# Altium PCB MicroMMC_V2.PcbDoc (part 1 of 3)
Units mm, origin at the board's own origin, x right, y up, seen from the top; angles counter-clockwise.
Board outline 100.01 x 100 mm, 4 copper layers (TOP01, GND02, POWER03, BOTTOM04); 302 components, 195 nets, 1017 pads, 817 vias.
Unrouted connection lines stored in the file: 7.
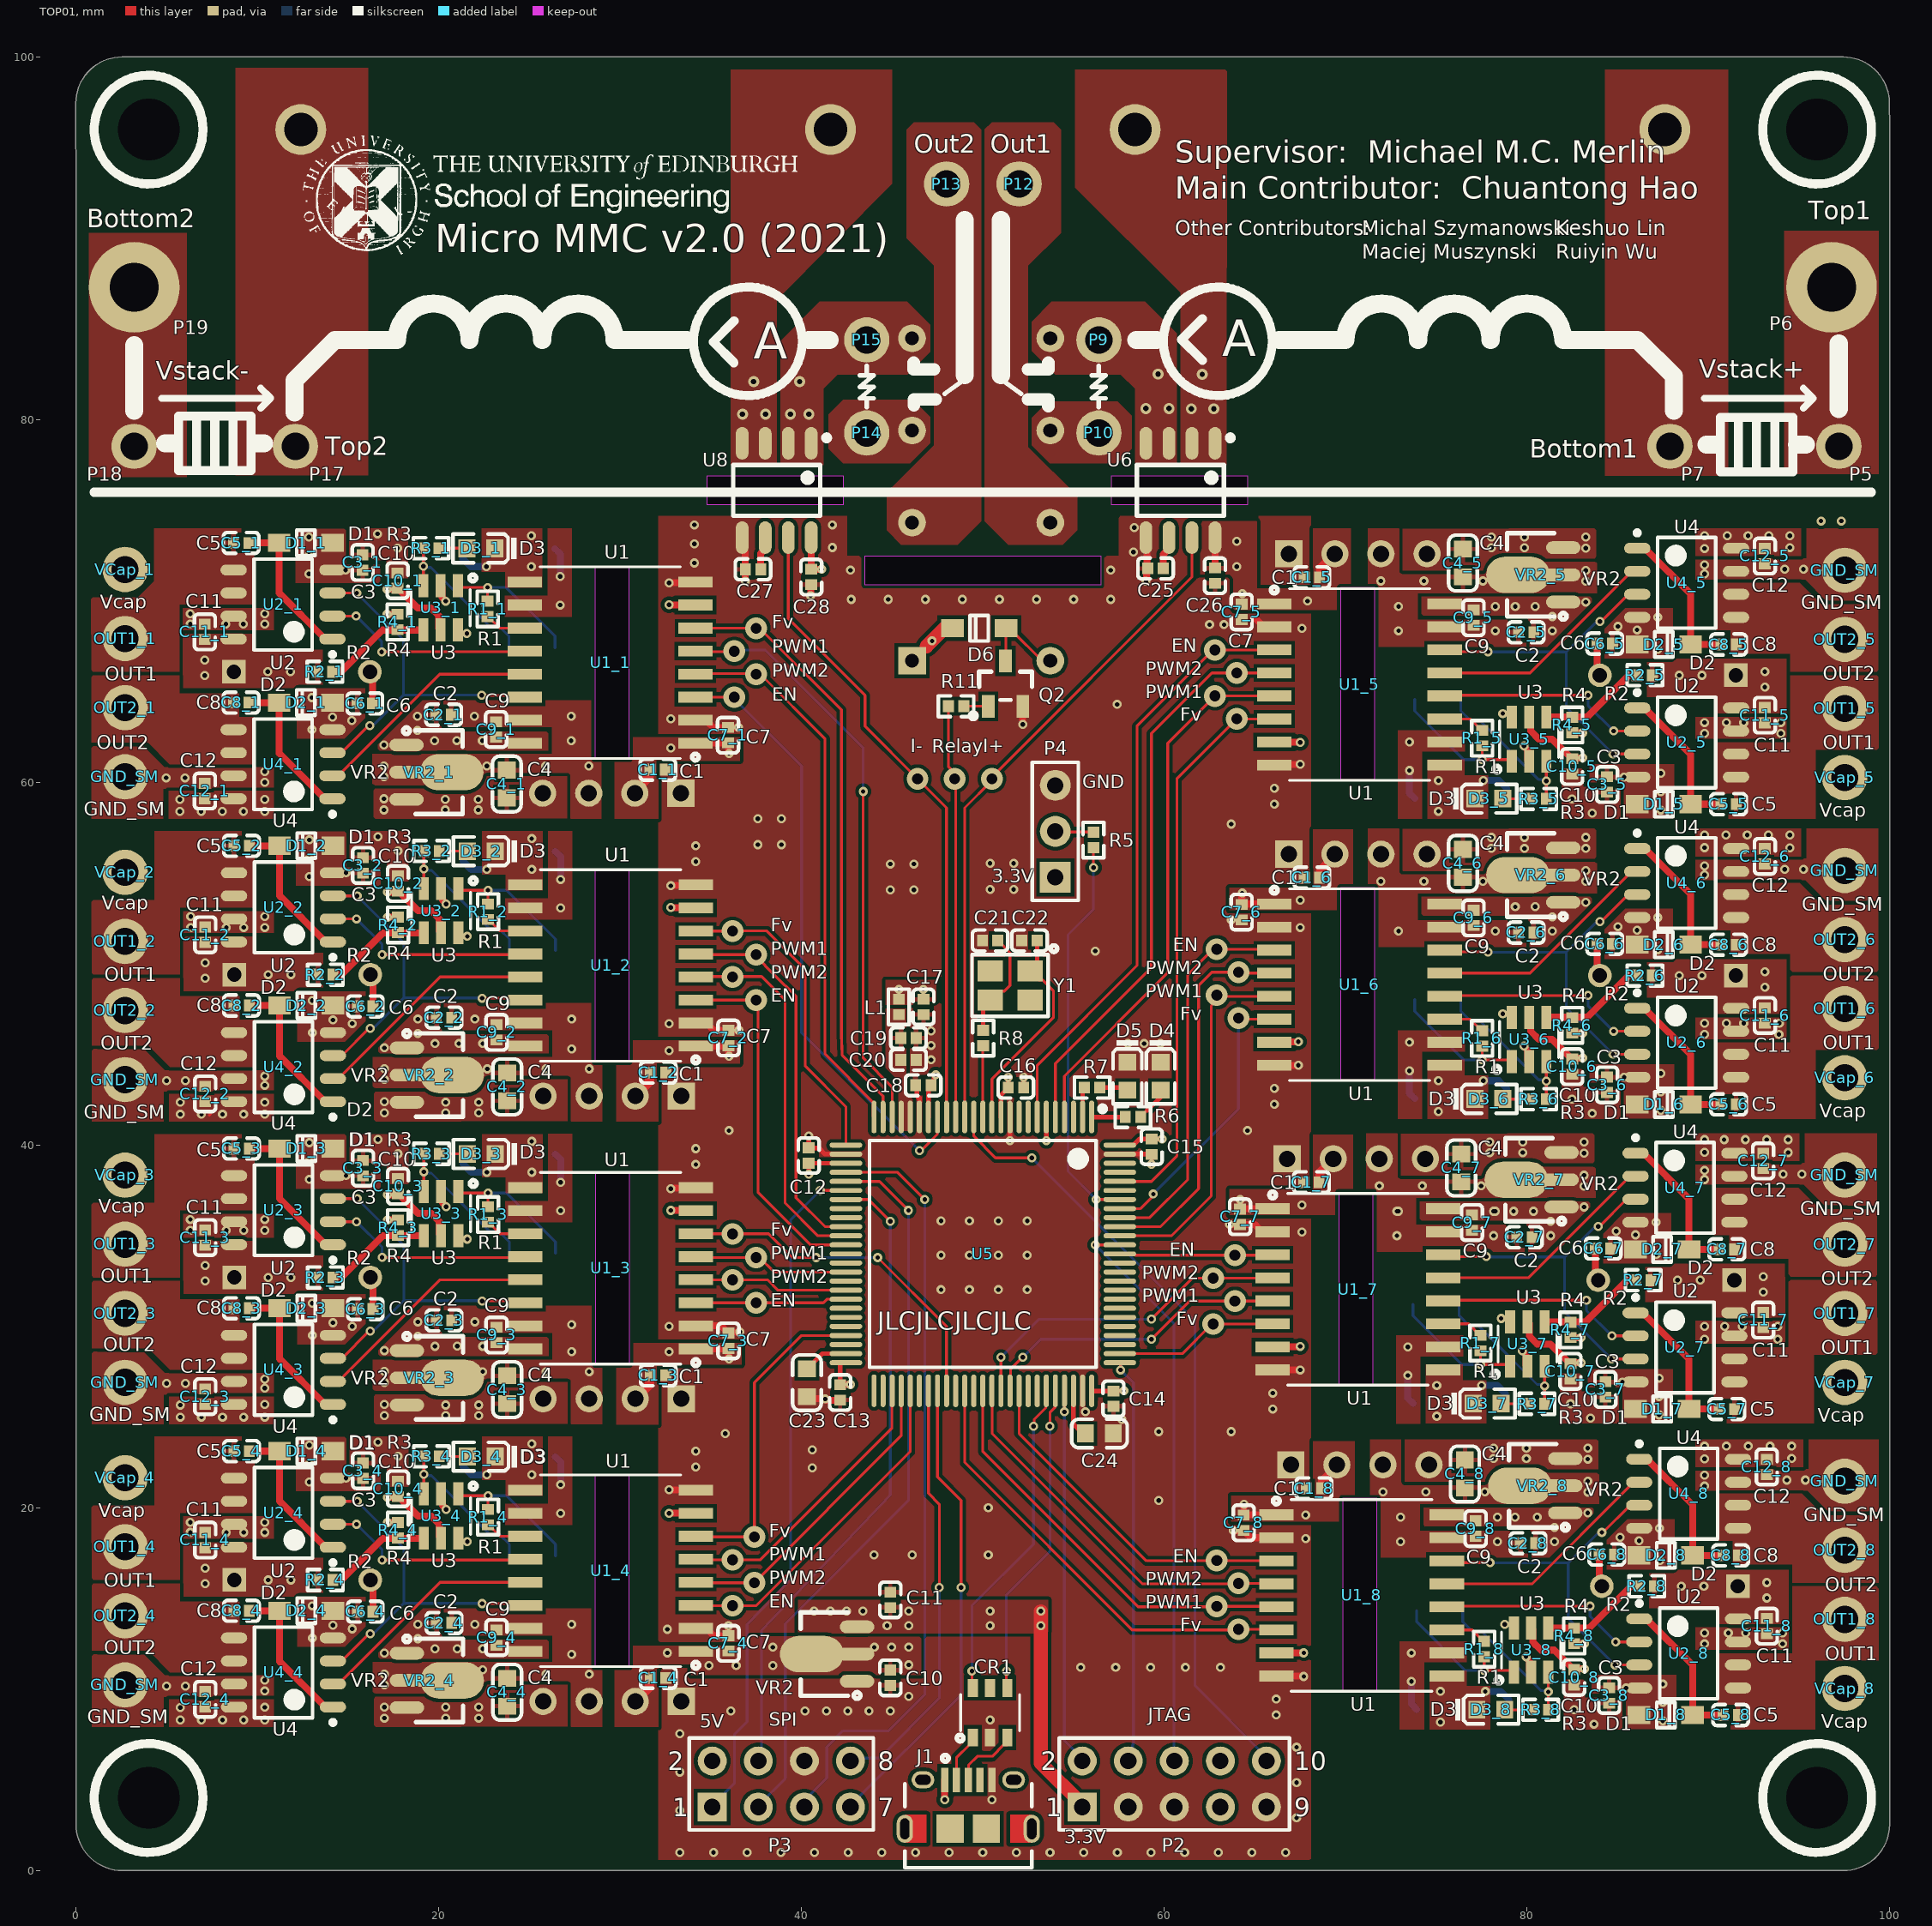
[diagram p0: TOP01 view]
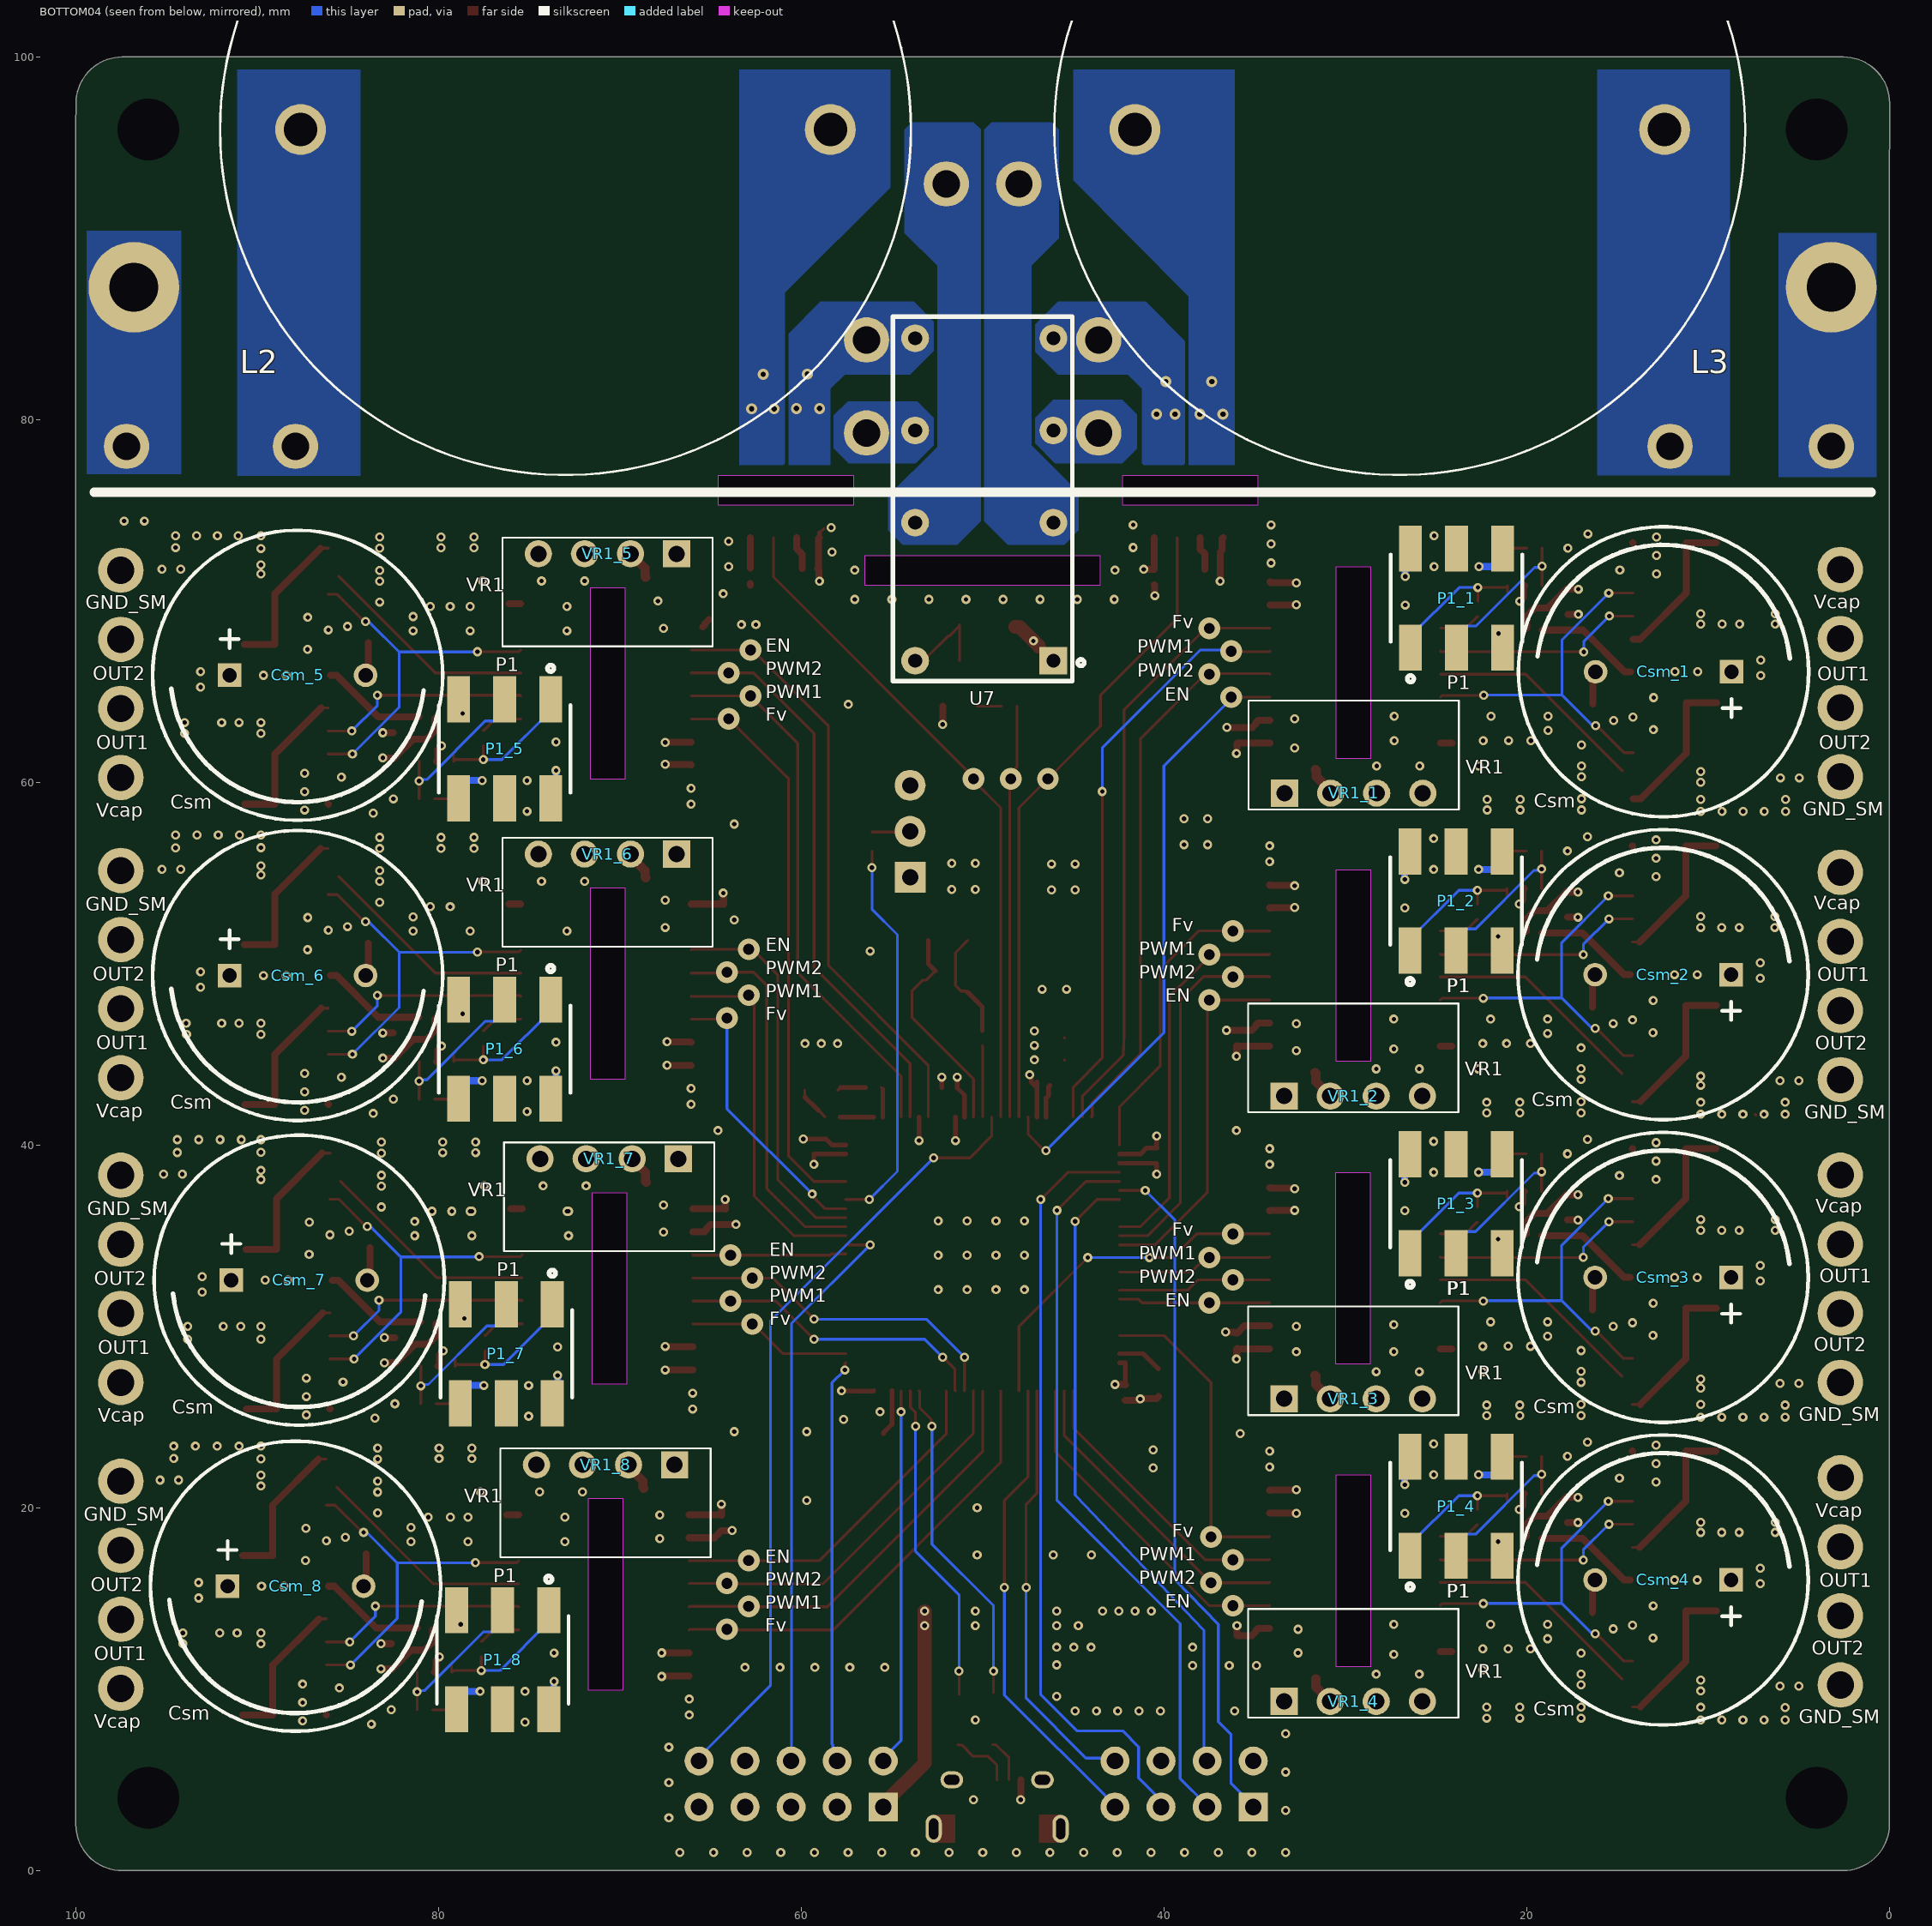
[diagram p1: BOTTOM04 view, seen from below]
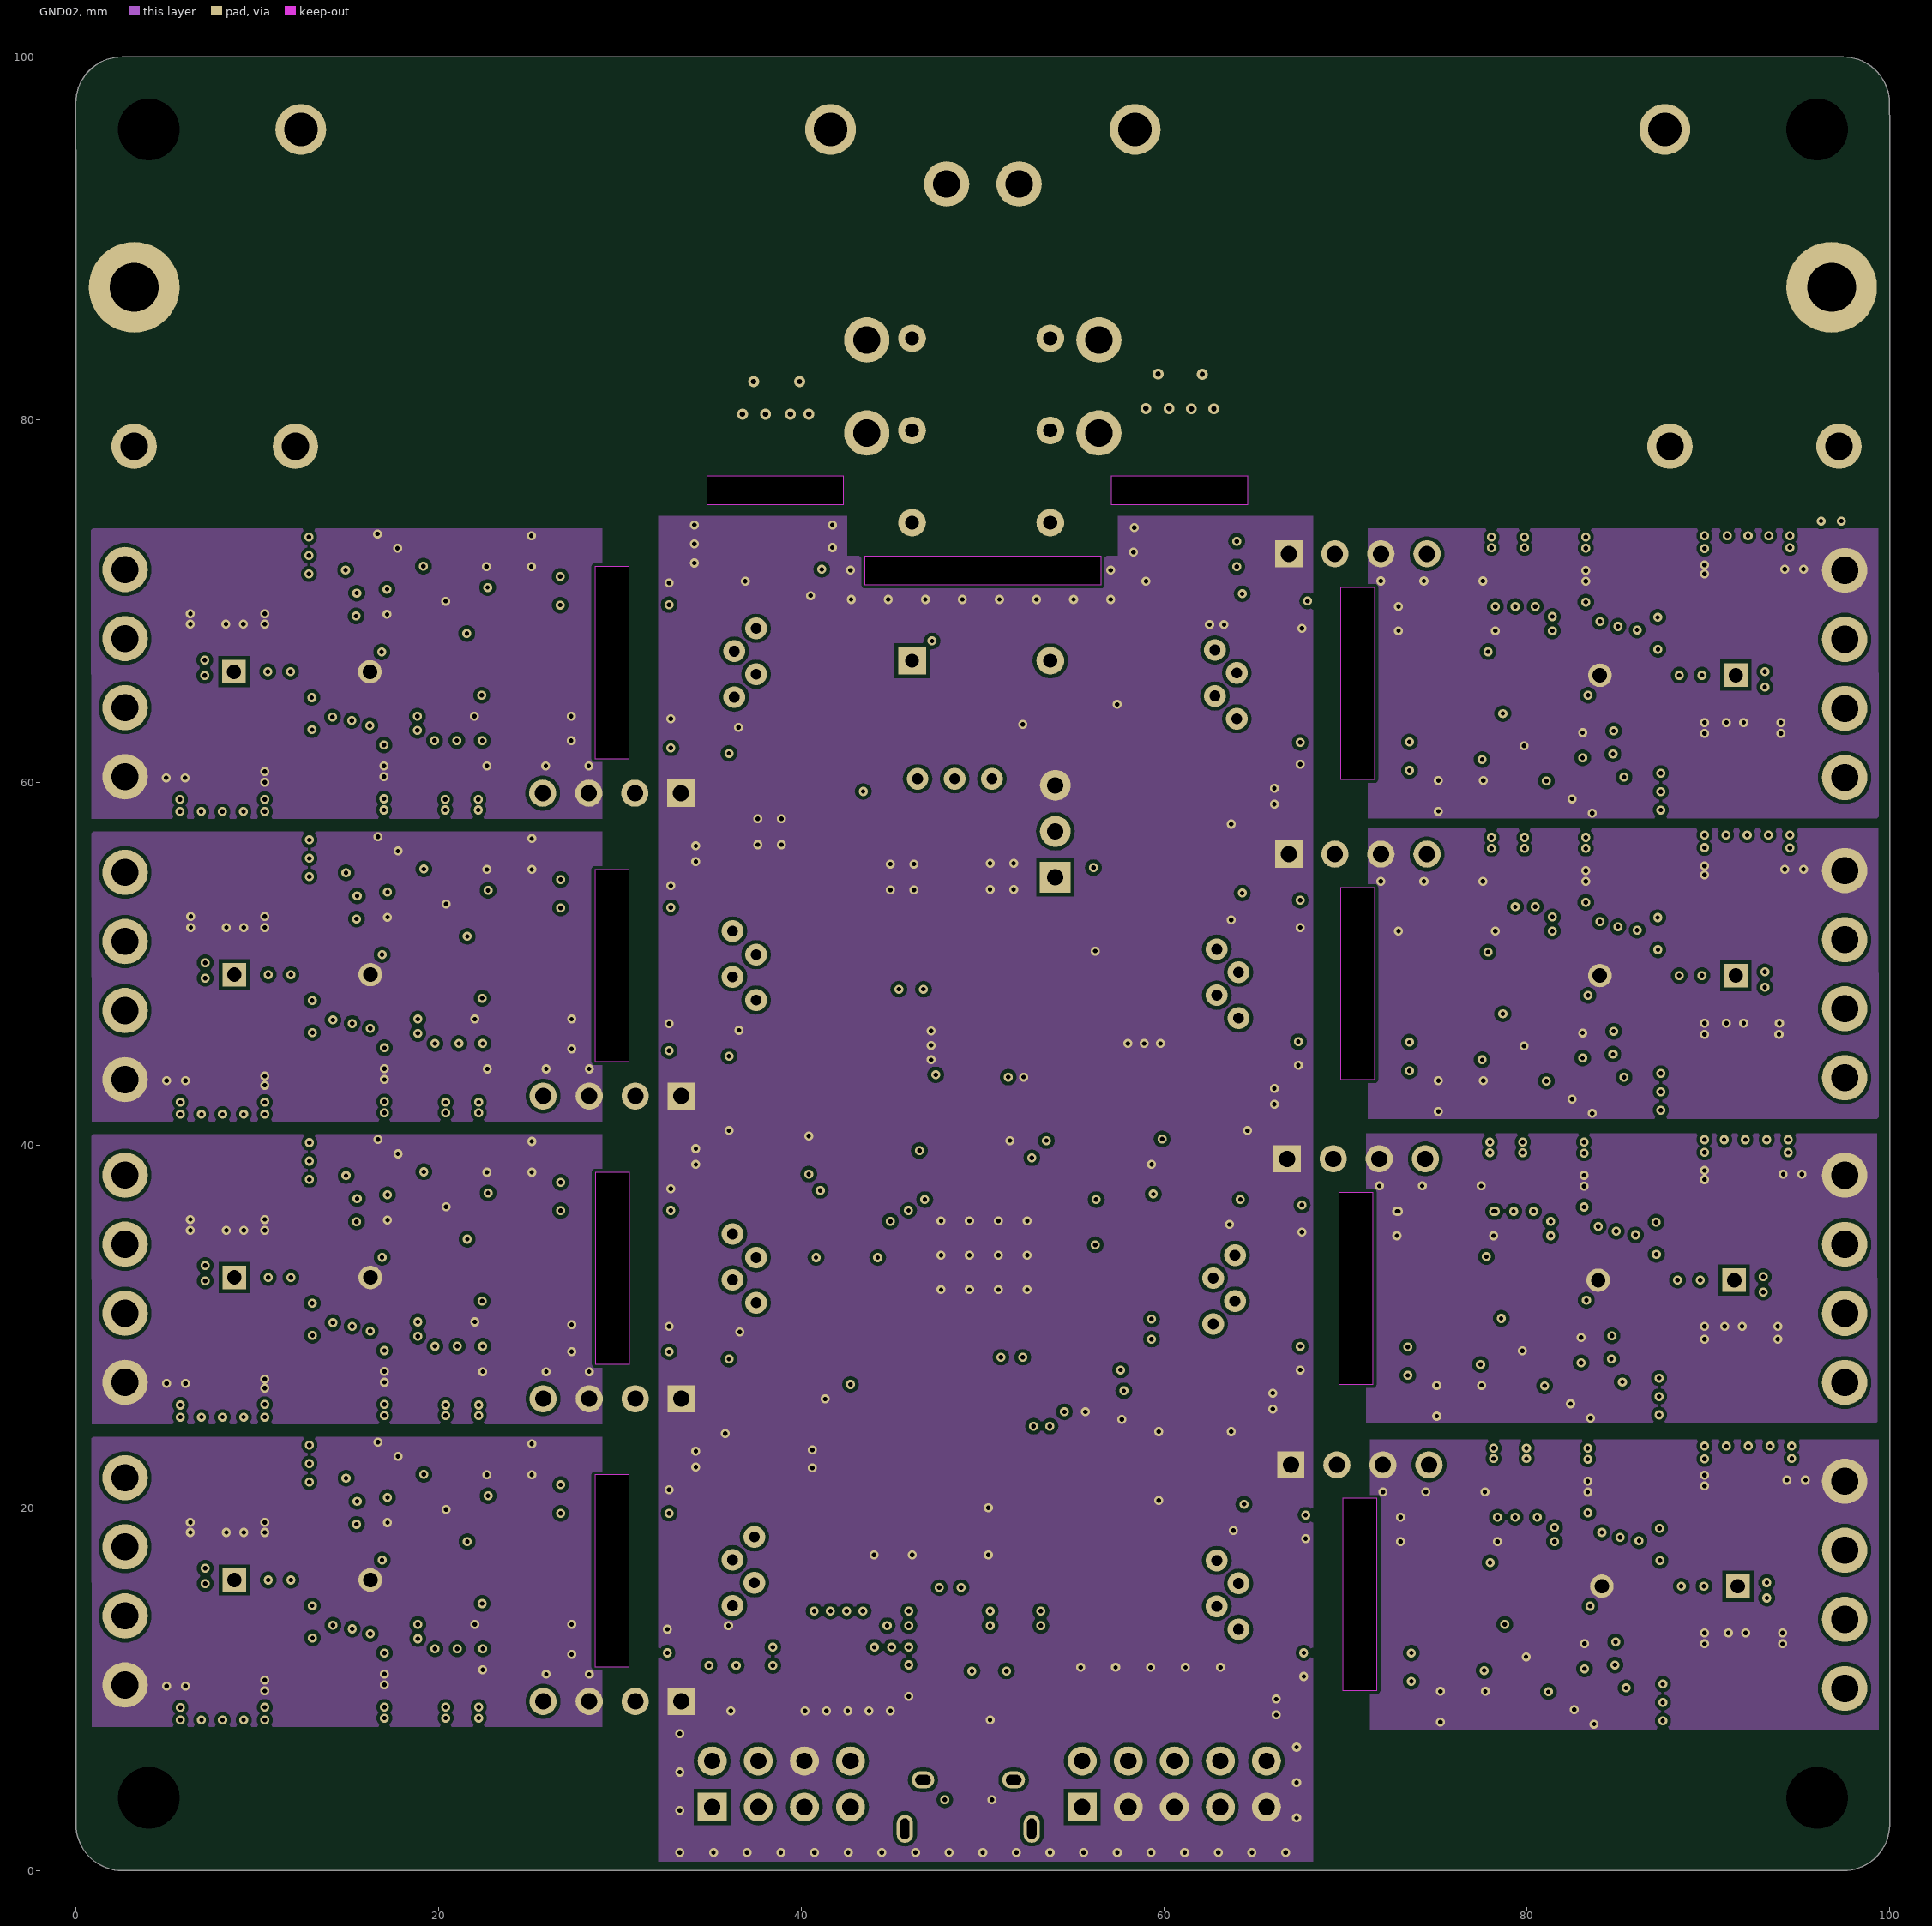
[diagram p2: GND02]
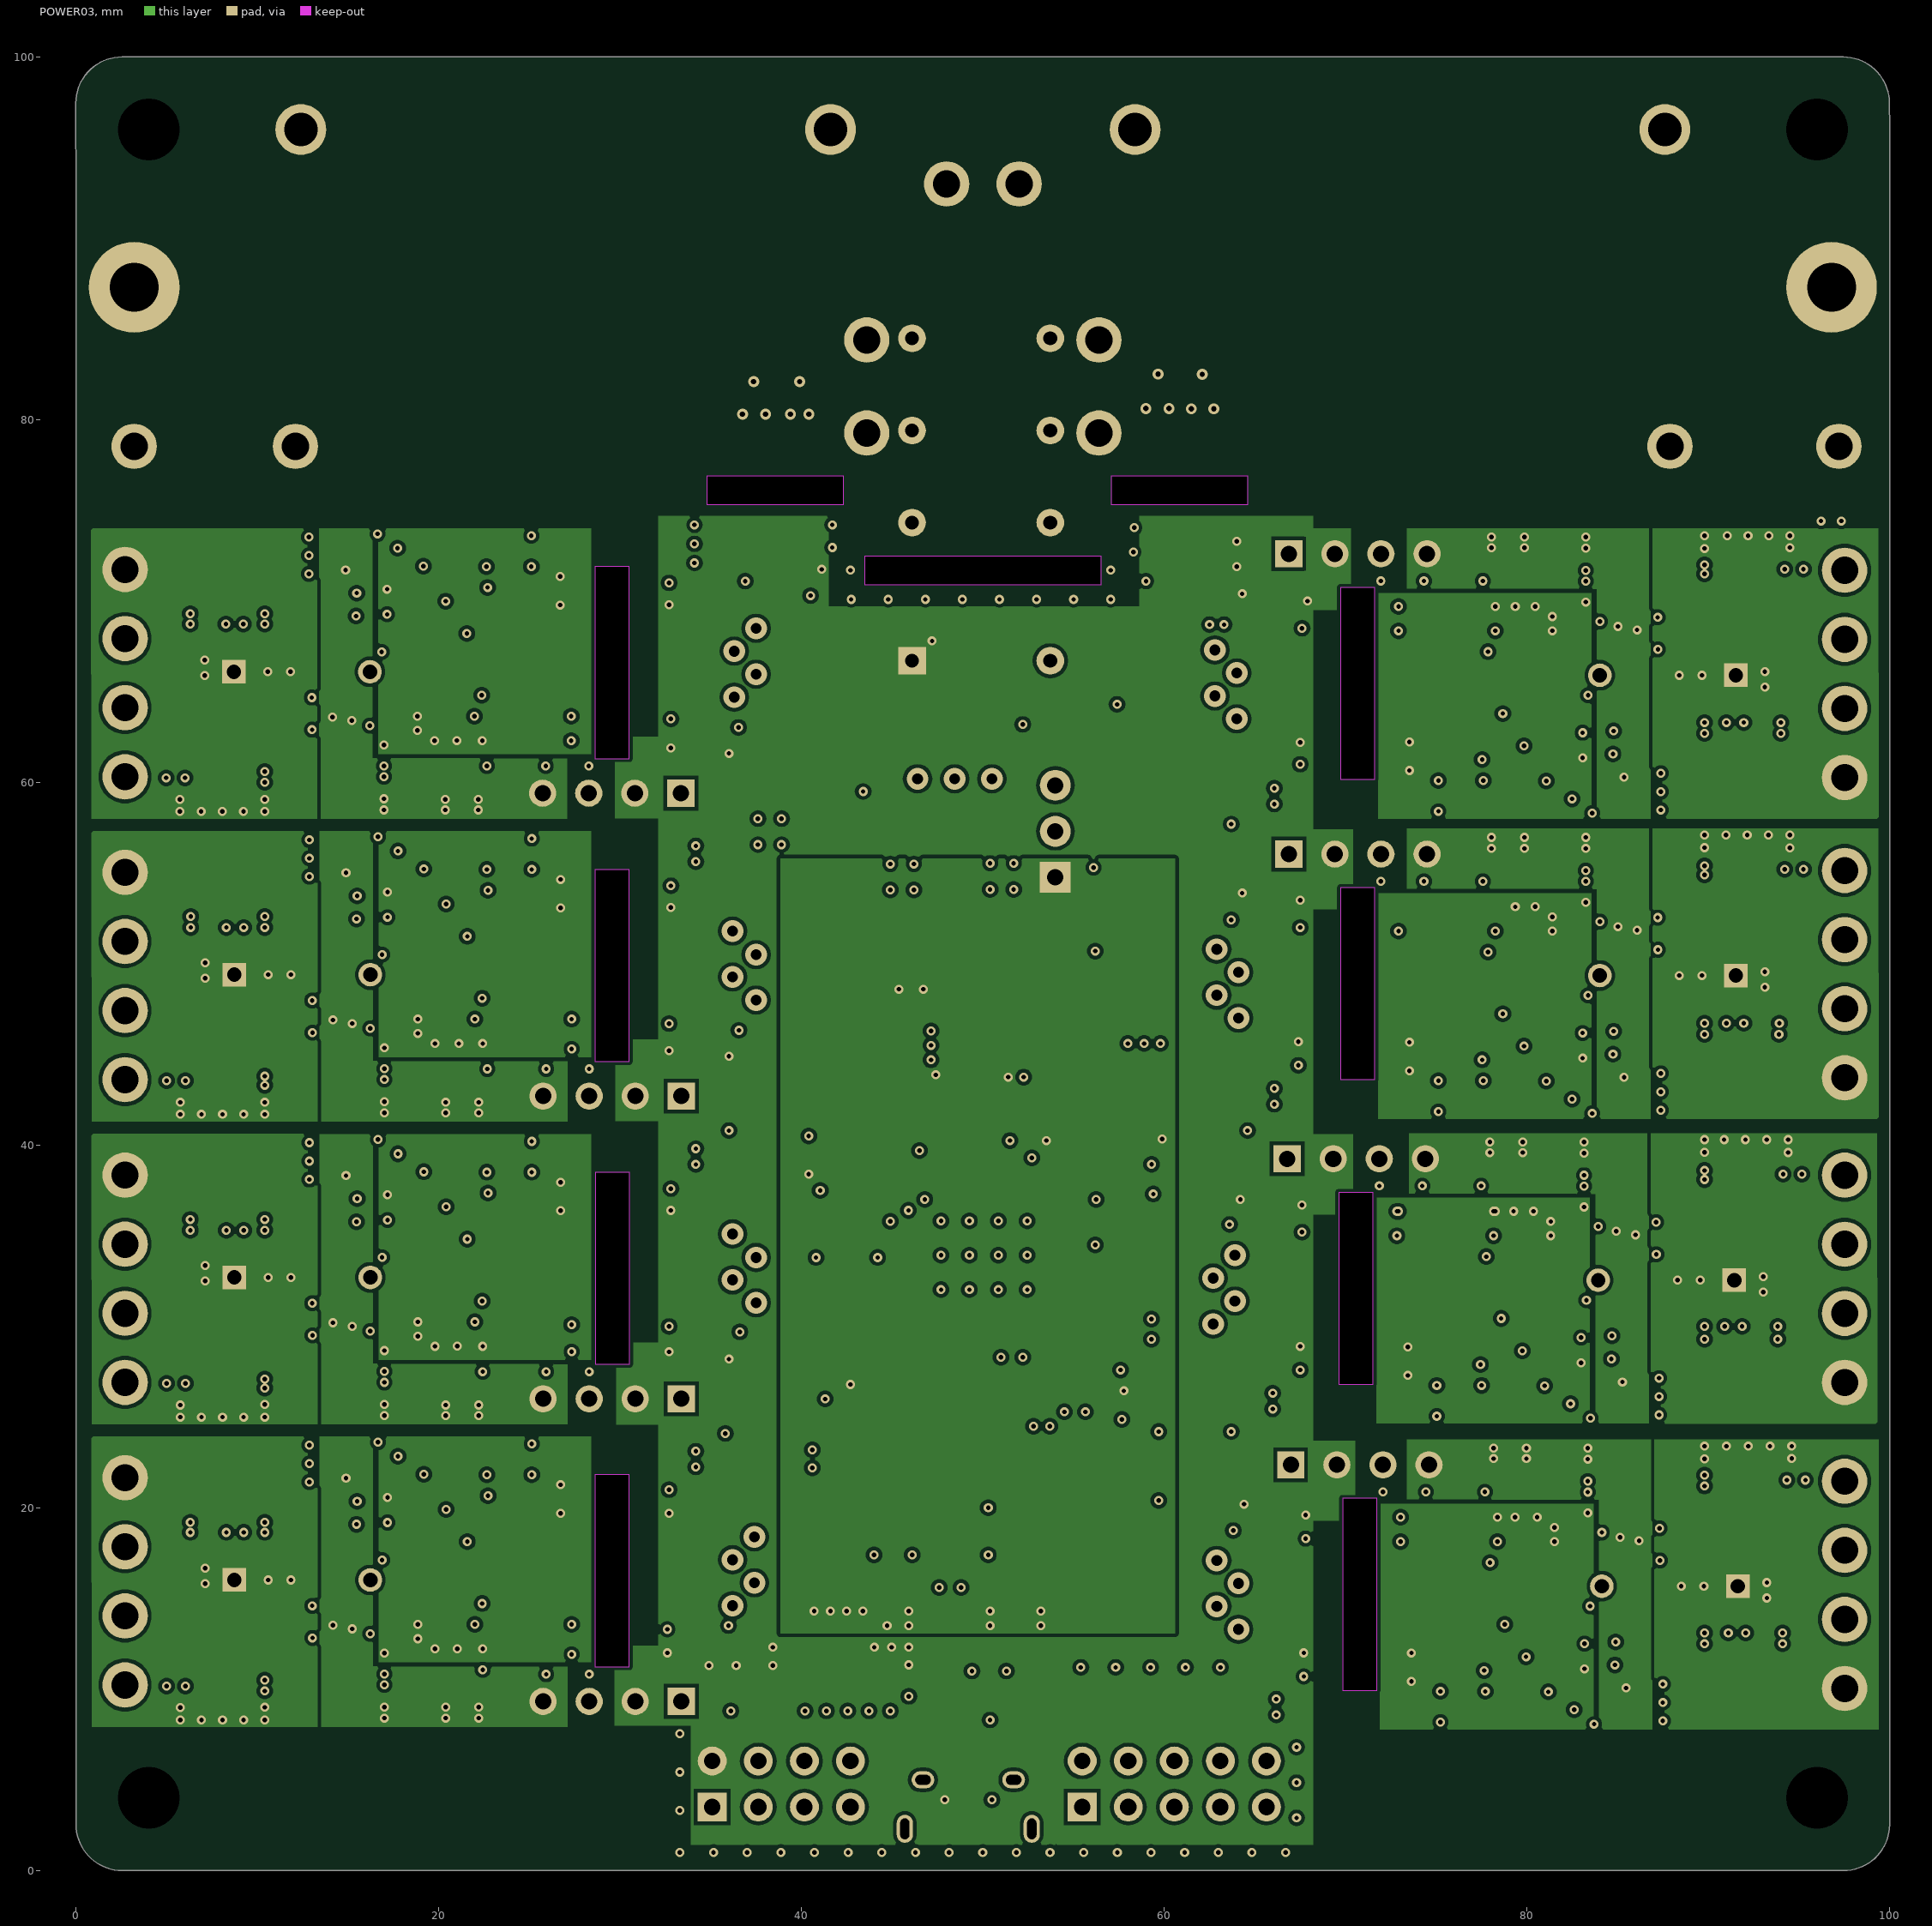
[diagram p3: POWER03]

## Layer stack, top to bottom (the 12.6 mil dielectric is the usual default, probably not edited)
Top Solder: solder mask 0.0102, Solder Resist, Dk 3.5
TOP01: signal copper 0.0356
Dielectric 1: dielectric 0.32, FR-4, Dk 4.8
GND02: signal copper 0.0356
Dielectric2: dielectric 0.32, FR-4, Dk 4.8
POWER03: signal copper 0.0356
Dielectric3: dielectric 0.32, FR-4, Dk 4.8
BOTTOM04: signal copper 0.0356
Bottom Solder: solder mask 0.0102, Solder Resist, Dk 3.5

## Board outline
2.54,0 cw(c2.54,2.54) 0,2.54 0,4.482 0,92.357 -0.012,97.46 cw(c2.528,97.46) 2.528,100 97.446,100 cw(c97.446,97.46) 99.986,97.46 100,96.167 100,2.537 cw(c97.46,2.537) 97.46,-0.003 95.335,0
cut-out: 34.8,76.9 42.3,76.9 42.3,75.3 34.8,75.3
cut-out: 71.733,9.939 71.733,20.517 69.833,20.517 69.833,9.939
cut-out: 71.532,26.813 71.532,37.391 69.632,37.391 69.632,26.813
cut-out: 71.623,43.613 71.623,54.191 69.723,54.191 69.723,43.613
cut-out: 71.623,60.169 71.623,70.747 69.723,70.747 69.723,60.169
cut-out: 28.6,21.814 28.6,11.236 30.5,11.236 30.5,21.814
cut-out: 28.624,38.499 28.624,27.921 30.524,27.921 30.524,38.499
cut-out: 28.6,71.894 28.6,61.316 30.5,61.316 30.5,71.894
cut-out: 28.6,55.189 28.6,44.611 30.5,44.611 30.5,55.189
cut-out: 43.5,72.492 56.5,72.492 56.5,70.892 43.5,70.892
cut-out: 57.1,76.9 64.6,76.9 64.6,75.3 57.1,75.3

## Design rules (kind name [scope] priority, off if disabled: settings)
Clearance [All] p1: gap=0.2 ignorepadtopadclearanceinfootprint=FALSE except(0.254: Via-Via)
Height [All] p1: minheight=0 maxheight=100 prefheight=12.7
HoleSize [All] p1: absolutevalues=TRUE maxlimit=6 minlimit=0.25 maxpercent=80.000 minpercent=20.000
HoleToHoleClearance [All] p1: gap=0.6 allowstackedmicrovias=TRUE
PlaneConnect [All] p1: planeconnectstyle=Direct reliefexpansion=0.508 reliefentries=4 reliefconductorwidth=0.254 reliefairgap=0.254
PolygonConnect [All] p1: connectstyle=Direct reliefconductorwidth=0.254 reliefentries=4 polygonreliefangle="90 Angle" airgapwidth=0.254
RoomDefinition 5 [InComponentClass('5')] p1: confinementstyle=ConfineIn formatcopy=TRUE lockcomponents=TRUE outline 63.5,74.297 99.289,74.297 99.289,57.7 63.5,57.7
RoomDefinition 8 [InComponentClass('8')] p2: confinementstyle=ConfineIn formatcopy=TRUE lockcomponents=FALSE outline 63.61,24.067 99.399,24.067 99.399,7.47 63.61,7.47
RoomDefinition 1 [InComponentClass('1')] p3: confinementstyle=ConfineIn formatcopy=TRUE lockcomponents=FALSE outline 0.611,74.297 36.4,74.297 36.4,57.7 0.611,57.7
RoomDefinition 2 [InComponentClass('2')] p4: confinementstyle=ConfineIn formatcopy=TRUE lockcomponents=FALSE outline 0.635,57.597 36.424,57.597 36.424,41 0.635,41
RoomDefinition 3 [InComponentClass('3')] p5: confinementstyle=ConfineIn formatcopy=TRUE lockcomponents=FALSE outline 0.635,40.902 36.424,40.902 36.424,24.305 0.635,24.305
RoomDefinition 4 [InComponentClass('4')] p6: confinementstyle=ConfineIn formatcopy=TRUE lockcomponents=FALSE outline 0.635,24.217 36.424,24.217 36.424,7.62 0.635,7.62
RoomDefinition 7 [InComponentClass('7')] p7: confinementstyle=ConfineIn formatcopy=TRUE lockcomponents=FALSE outline 63.409,40.941 99.198,40.941 99.198,24.344 63.409,24.344
RoomDefinition 6 [InComponentClass('6')] p8: confinementstyle=ConfineIn formatcopy=TRUE lockcomponents=FALSE outline 63.5,57.741 99.289,57.741 99.289,41.144 63.5,41.144
RoutingVias [All] p1: holewidth=1 width=2 viastyle="Through Hole" minholewidth=0.25 minwidth=0.5 maxholewidth=6 maxwidth=12
SolderMaskExpansion [All] p1: expansion=0.102 istentingtop=FALSE
UnRoutedNet [All] p1: checkbadconnections=TRUE
Width [All] p1: maxlimit=0.762 minlimit=0.152 preferedwidth=0.152
25 further rules are at their usual default settings.

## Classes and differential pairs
channel class SM_V2: 1 2 3 4 5 6 7 8
component class 2: C1_2 C2_2 C3_2 C4_2 C5_2 C6_2 C7_2 C8_2 C9_2 C10_2 C11_2 C12_2 Csm_2 D1_2 D2_2 D3_2 GND1_2 P1_2 R1_2 R2_2 R3_2 R4_2 U1_2 U2_2 U3_2 U4_2 Vcap1_2 VR1_2 VR2_2
net class TIM_Fv[8..1]: TIM_Fv1 TIM_Fv2 TIM_Fv3 TIM_Fv4 TIM_Fv5 TIM_Fv6 TIM_Fv7 TIM_Fv8
net class PWM_IN2[8..1]: PWM_IN21 PWM_IN22 PWM_IN23 PWM_IN24 PWM_IN25 PWM_IN26 PWM_IN27 PWM_IN28
net class PWM_IN1[8..1]: PWM_IN11 PWM_IN12 PWM_IN13 PWM_IN14 PWM_IN15 PWM_IN16 PWM_IN17 PWM_IN18
net class GPIO_EN[8..1]: GPIO_EN1 GPIO_EN2 GPIO_EN3 GPIO_EN4 GPIO_EN5 GPIO_EN6 GPIO_EN7 GPIO_EN8
component class Stack_V2: C25 C26 C27 C28 D6 L2 L3 P5 P6 P7 P9 P10 P12 P13 P14 P15 P17 P18 P19 Q2 R11 U6 U7 U8
component class StackController_V2: C10 C11 C12 C13 C14 C15 C16 C17 C18 C19 C20 C21 C22 C23 C24 CR1 D4 D5 J1 L1 P2 P3 P4 R5 R6 R7 R8 U5 VR2 Y1
component class 8: C1_8 C2_8 C3_8 C4_8 C5_8 C6_8 C7_8 C8_8 C9_8 C10_8 C11_8 C12_8 Csm_8 D1_8 D2_8 D3_8 GND1_8 P1_8 R1_8 R2_8 R3_8 R4_8 U1_8 U2_8 U3_8 U4_8 Vcap1_8 VR1_8 VR2_8
component class 7: C1_7 C2_7 C3_7 C4_7 C5_7 C6_7 C7_7 C8_7 C9_7 C10_7 C11_7 C12_7 Csm_7 D1_7 D2_7 D3_7 GND1_7 OUT1_7 P1_7 R1_7 R2_7 R3_7 R4_7 U1_7 U2_7 U3_7 U4_7 Vcap1_7 VR1_7 VR2_7
component class 6: C1_6 C2_6 C3_6 C4_6 C5_6 C6_6 C7_6 C8_6 C9_6 C10_6 C11_6 C12_6 Csm_6 D1_6 D2_6 D3_6 GND1_6 P1_6 R1_6 R2_6 R3_6 R4_6 U1_6 U2_6 U3_6 U4_6 Vcap1_6 VR1_6 VR2_6
component class 5: C1_5 C2_5 C3_5 C4_5 C5_5 C6_5 C7_5 C8_5 C9_5 C10_5 C11_5 C12_5 Csm_5 D1_5 D2_5 D3_5 GND1_5 OUT1_5 P1_5 R1_5 R2_5 R3_5 R4_5 U1_5 U2_5 U3_5 U4_5 Vcap1_2 Vcap1_5 VR1_5 VR2_5
component class 4: C1_4 C2_4 C3_4 C4_4 C5_4 C6_4 C7_4 C8_4 C9_4 C10_4 C11_4 C12_4 Csm_4 D1_4 D2_4 D3_4 GND1_4 P1_4 R1_4 R2_4 R3_4 R4_4 U1_4 U2_4 U3_4 U4_4 Vcap1_4 VR1_4 VR2_4
component class 3: C1_3 C2_3 C3_3 C4_3 C5_3 C6_3 C7_3 C8_3 C9_3 C10_3 C11_3 C12_3 Csm_3 D1_3 D2_3 D3_3 GND1_3 OUT1_3 P1_3 R1_3 R2_3 R3_3 R4_3 U1_3 U2_3 U3_3 U4_3 Vcap1_3 VR1_3 VR2_3
component class 1: C1_1 C2_1 C3_1 C4_1 C5_1 C6_1 C7_1 C8_1 C9_1 C10_1 C11_1 C12_1 Csm_1 D1_1 D2_1 D3_1 GND1_1 OUT1_1 P1_1 R1_1 R2_1 R3_1 R4_1 U1_1 U2_1 U3_1 U4_1 Vcap1_1 VR1_1 VR2_1

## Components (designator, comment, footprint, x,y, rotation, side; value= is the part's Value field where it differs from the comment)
C1_1 "10uF (106) ±20% 6.3V X5R" 0402_C 32.075,60.7 r180 top (schematic designator C1)
C1_2 "10uF (106) ±20% 6.3V X5R" 0402_C 32.099,44 r180 top (schematic designator C1)
C1_3 "10uF (106) ±20% 6.3V X5R" 0402_C 32.099,27.305 r180 top (schematic designator C1)
C1_4 "10uF (106) ±20% 6.3V X5R" 0402_C 32.099,10.62 r180 top (schematic designator C1)
C1_5 "10uF (106) ±20% 6.3V X5R" 0402_C 68.148,71.307 r0 top (schematic designator C1)
C1_6 "10uF (106) ±20% 6.3V X5R" 0402_C 68.148,54.751 r0 top (schematic designator C1)
C1_7 "10uF (106) ±20% 6.3V X5R" 0402_C 68.123,37.951 r0 top (schematic designator C1)
C1_8 "10uF (106) ±20% 6.3V X5R" 0402_C 68.258,21.077 r0 top (schematic designator C1)
C2_1 "10uF (106) ±20% 6.3V X5R" 0402_C 20.267,63.73 r180 top (schematic designator C2)
C2_2 "10uF (106) ±20% 6.3V X5R" 0402_C 20.291,47.03 r180 top (schematic designator C2)
C2_3 "10uF (106) ±20% 6.3V X5R" 0402_C 20.291,30.335 r180 top (schematic designator C2)
C2_4 "10uF (106) ±20% 6.3V X5R" 0402_C 20.291,13.65 r180 top (schematic designator C2)
C2_5 "10uF (106) ±20% 6.3V X5R" 0402_C 79.955,68.277 r0 top (schematic designator C2)
C2_6 "10uF (106) ±20% 6.3V X5R" 0402_C 79.955,51.721 r0 top (schematic designator C2)
C2_7 "10uF (106) ±20% 6.3V X5R" 0402_C 79.864,34.921 r0 top (schematic designator C2)
C2_8 "10uF (106) ±20% 6.3V X5R" 0402_C 80.066,18.047 r0 top (schematic designator C2)
C3_1 "1uF (105) ±10% 25V X5R" 0402_C 15.8,72.125 r270 top (schematic designator C3)
C3_2 "1uF (105) ±10% 25V X5R" 0402_C 15.824,55.425 r270 top (schematic designator C3)
C3_3 "1uF (105) ±10% 25V X5R" 0402_C 15.824,38.73 r270 top (schematic designator C3)
C3_4 "1uF (105) ±10% 25V X5R" 0402_C 15.824,22.045 r270 top (schematic designator C3)
C3_5 "1uF (105) ±10% 25V X5R" 0402_C 84.423,59.882 r90 top (schematic designator C3)
C3_6 "1uF (105) ±10% 25V X5R" 0402_C 84.423,43.326 r90 top (schematic designator C3)
C3_7 "1uF (105) ±10% 25V X5R" 0402_C 84.332,26.526 r90 top (schematic designator C3)
C3_8 "1uF (105) ±10% 25V X5R" 0402_C 84.533,9.652 r90 top (schematic designator C3)
C4_1 "10uF 16V" 0603_C 23.75,59.91 r270 top (schematic designator C4)
C4_2 "10uF 16V" 0603_C 23.773,43.21 r270 top (schematic designator C4)
C4_3 "10uF 16V" 0603_C 23.773,26.515 r270 top (schematic designator C4)
C4_4 "10uF 16V" 0603_C 23.773,9.83 r270 top (schematic designator C4)
C4_5 "10uF 16V" 0603_C 76.473,72.096 r90 top (schematic designator C4)
C4_6 "10uF 16V" 0603_C 76.473,55.54 r90 top (schematic designator C4)
C4_7 "10uF 16V" 0603_C 76.382,38.74 r90 top (schematic designator C4)
C4_8 "10uF 16V" 0603_C 76.583,21.866 r90 top (schematic designator C4)
C5_1 "1uF (105) ±10% 25V X5R" 0402_C 9.1,73.205 r180 top (schematic designator C5)
C5_2 "1uF (105) ±10% 25V X5R" 0402_C 9.124,56.505 r180 top (schematic designator C5)
C5_3 "1uF (105) ±10% 25V X5R" 0402_C 9.124,39.81 r180 top (schematic designator C5)
C5_4 "1uF (105) ±10% 25V X5R" 0402_C 9.124,23.125 r180 top (schematic designator C5)
C5_5 "1uF (105) ±10% 25V X5R" 0402_C 91.123,58.802 r0 top (schematic designator C5)
C5_6 "1uF (105) ±10% 25V X5R" 0402_C 91.123,42.246 r0 top (schematic designator C5)
C5_7 "1uF (105) ±10% 25V X5R" 0402_C 91.032,25.446 r0 top (schematic designator C5)
C5_8 "1uF (105) ±10% 25V X5R" 0402_C 91.233,8.572 r0 top (schematic designator C5)
C6_1 "1uF (105) ±10% 25V X5R" 0402_C 15.925,64.352 r180 top (schematic designator C6)
C6_2 "1uF (105) ±10% 25V X5R" 0402_C 15.949,47.652 r180 top (schematic designator C6)
C6_3 "1uF (105) ±10% 25V X5R" 0402_C 15.949,30.957 r180 top (schematic designator C6)
C6_4 "1uF (105) ±10% 25V X5R" 0402_C 15.949,14.272 r180 top (schematic designator C6)
C6_5 "1uF (105) ±10% 25V X5R" 0402_C 84.298,67.655 r0 top (schematic designator C6)
C6_6 "1uF (105) ±10% 25V X5R" 0402_C 84.298,51.099 r0 top (schematic designator C6)
C6_7 "1uF (105) ±10% 25V X5R" 0402_C 84.207,34.299 r0 top (schematic designator C6)
C6_8 "1uF (105) ±10% 25V X5R" 0402_C 84.408,17.425 r0 top (schematic designator C6)
C7_1 "100nF (104) ±10% 16V X7R" 0402_C 35.95,62.605 r270 top (schematic designator C7)
C7_2 "100nF (104) ±10% 16V X7R" 0402_C 35.973,45.905 r270 top (schematic designator C7)
C7_3 "100nF (104) ±10% 16V X7R" 0402_C 35.973,29.21 r270 top (schematic designator C7)
C7_4 "100nF (104) ±10% 16V X7R" 0402_C 35.973,12.525 r270 top (schematic designator C7)
C7_5 "100nF (104) ±10% 16V X7R" 0402_C 64.273,69.402 r90 top (schematic designator C7)
C7_6 "100nF (104) ±10% 16V X7R" 0402_C 64.273,52.846 r90 top (schematic designator C7)
C7_7 "100nF (104) ±10% 16V X7R" 0402_C 64.182,36.046 r90 top (schematic designator C7)
C7_8 "100nF (104) ±10% 16V X7R" 0402_C 64.383,19.172 r90 top (schematic designator C7)
C8_1 "1uF (105) ±10% 25V X5R" 0402_C 9.1,64.4 r180 top (schematic designator C8)
C8_2 "1uF (105) ±10% 25V X5R" 0402_C 9.124,47.7 r180 top (schematic designator C8)
C8_3 "1uF (105) ±10% 25V X5R" 0402_C 9.124,31.005 r180 top (schematic designator C8)
C8_4 "1uF (105) ±10% 25V X5R" 0402_C 9.124,14.32 r180 top (schematic designator C8)
C8_5 "1uF (105) ±10% 25V X5R" 0402_C 91.123,67.607 r0 top (schematic designator C8)
C8_6 "1uF (105) ±10% 25V X5R" 0402_C 91.123,51.051 r0 top (schematic designator C8)
C8_7 "1uF (105) ±10% 25V X5R" 0402_C 91.032,34.251 r0 top (schematic designator C8)
C8_8 "1uF (105) ±10% 25V X5R" 0402_C 91.233,17.377 r0 top (schematic designator C8)
C9_1 "100nF (104) ±10% 16V X7R" 0402_C 23.16,62.922 r270 top (schematic designator C9)
C9_2 "100nF (104) ±10% 16V X7R" 0402_C 23.184,46.222 r270 top (schematic designator C9)
C9_3 "100nF (104) ±10% 16V X7R" 0402_C 23.184,29.527 r270 top (schematic designator C9)
C9_4 "100nF (104) ±10% 16V X7R" 0402_C 23.184,12.842 r270 top (schematic designator C9)
C9_5 "100nF (104) ±10% 16V X7R" 0402_C 77.063,69.085 r90 top (schematic designator C9)
C9_6 "100nF (104) ±10% 16V X7R" 0402_C 77.063,52.529 r90 top (schematic designator C9)
C9_7 "100nF (104) ±10% 16V X7R" 0402_C 76.972,35.729 r90 top (schematic designator C9)
C9_8 "100nF (104) ±10% 16V X7R" 0402_C 77.173,18.855 r90 top (schematic designator C9)
C10 "10uF (106) ±20% 6.3V X5R" 0402_C 44.9,10.625 r90 top
C10_1 "100nF (104) ±10% 16V X7R" 0402_C 17.725,71.127 r270 top (schematic designator C10)
C10_2 "100nF (104) ±10% 16V X7R" 0402_C 17.749,54.427 r270 top (schematic designator C10)
C10_3 "100nF (104) ±10% 16V X7R" 0402_C 17.749,37.731 r270 top (schematic designator C10)
C10_4 "100nF (104) ±10% 16V X7R" 0402_C 17.749,21.047 r270 top (schematic designator C10)
C10_5 "100nF (104) ±10% 16V X7R" 0402_C 82.498,60.88 r90 top (schematic designator C10)
C10_6 "100nF (104) ±10% 16V X7R" 0402_C 82.498,44.324 r90 top (schematic designator C10)
C10_7 "100nF (104) ±10% 16V X7R" 0402_C 82.407,27.524 r90 top (schematic designator C10)
C10_8 "100nF (104) ±10% 16V X7R" 0402_C 82.608,10.65 r90 top (schematic designator C10)
C11 "10uF (106) ±20% 6.3V X5R" 0402_C 44.9,14.925 r270 top
C11_1 "1uF (105) ±10% 25V X5R" 0402_C 7.1,68.3 r270 top (schematic designator C11)
C11_2 "1uF (105) ±10% 25V X5R" 0402_C 7.124,51.6 r270 top (schematic designator C11)
C11_3 "1uF (105) ±10% 25V X5R" 0402_C 7.124,34.905 r270 top (schematic designator C11)
C11_4 "1uF (105) ±10% 25V X5R" 0402_C 7.124,18.22 r270 top (schematic designator C11)
C11_5 "1uF (105) ±10% 25V X5R" 0402_C 93.123,63.707 r90 top (schematic designator C11)
C11_6 "1uF (105) ±10% 25V X5R" 0402_C 93.123,47.151 r90 top (schematic designator C11)
C11_7 "1uF (105) ±10% 25V X5R" 0402_C 93.032,30.351 r90 top (schematic designator C11)
C11_8 "1uF (105) ±10% 25V X5R" 0402_C 93.233,13.477 r90 top (schematic designator C11)
C12 "4.7uF (475) ±20% 10V X5R" 0402_C 40.4,39.425 r270 top
C12_1 "1uF (105) ±10% 25V X5R" 0402_C 7.1,59.525 r270 top (schematic designator C12)
C12_2 "1uF (105) ±10% 25V X5R" 0402_C 7.124,42.825 r270 top (schematic designator C12)
C12_3 "1uF (105) ±10% 25V X5R" 0402_C 7.124,26.13 r270 top (schematic designator C12)
C12_4 "1uF (105) ±10% 25V X5R" 0402_C 7.124,9.445 r270 top (schematic designator C12)
C12_5 "1uF (105) ±10% 25V X5R" 0402_C 93.123,72.482 r90 top (schematic designator C12)
C12_6 "1uF (105) ±10% 25V X5R" 0402_C 93.123,55.926 r90 top (schematic designator C12)
C12_7 "1uF (105) ±10% 25V X5R" 0402_C 93.032,39.126 r90 top (schematic designator C12)
C12_8 "1uF (105) ±10% 25V X5R" 0402_C 93.233,22.252 r90 top (schematic designator C12)
C13 "100nF (104) ±10% 16V X7R" 0402_C 42.134,26.361 r90 top
C14 "100nF (104) ±10% 16V X7R" 0402_C 57.2,26.016 r90 top
C15 "100nF (104) ±10% 16V X7R" 0402_C 59.311,39.914 r90 top
C16 "100nF (104) ±10% 16V X7R" 0402_C 51.826,43.175 r180 top
C17 "100nF (104) ±10% 16V X7R" 0402_C 46.726,47.619 r90 top
C18 "100nF (104) ±10% 16V X7R" 0402_C 46.715,43.3 r0 top
C19 "1uF (105) ±10% 25V X5R" 0402_C 45.9,45.9 r0 top
C20 "100nF (104) ±10% 16V X7R" 0402_C 45.9,44.7 r180 top
C21 "12pF (120) ±5% 50V C0G" 0402_C 50.4,51.283 r0 top
C22 "12pF (120) ±5% 50V C0G" 0402_C 52.574,51.283 r0 top
C23 "2.2uF (225) ±10% 16V X5R" 0603_C 40.3,26.9 r90 top
C24 "2.2uF (225) ±10% 16V X5R" 0603_C 56.43,24.1 r180 top
C25 "1nF (102) ±10% 50V X7R" 0402_C 59.525,71.8 r0 top
C26 "100nF (104) ±10% 16V X7R" 0402_C 62.803,71.4 r90 top
C27 "1nF (102) ±10% 50V X7R" 0402_C 37.328,71.75 r0 top
C28 "100nF (104) ±10% 16V X7R" 0402_C 40.54,71.325 r90 top
CR1 "USBLC6-2SC6" SOT23-6L_STM 50.4,8.7 r0 top
Csm_1 "6800uF 16V" "6800UF 16V 16*25" 8.7,66.1 r0 bottom (schematic designator Csm)
Csm_2 "6800uF 16V" "6800UF 16V 16*25" 8.724,49.4 r0 bottom (schematic designator Csm)
Csm_3 "6800uF 16V" "6800UF 16V 16*25" 8.724,32.705 r0 bottom (schematic designator Csm)
Csm_4 "6800uF 16V" "6800UF 16V 16*25" 8.724,16.02 r0 bottom (schematic designator Csm)
Csm_5 "6800uF 16V" "6800UF 16V 16*25" 91.523,65.907 r180 bottom (schematic designator Csm)
Csm_6 "6800uF 16V" "6800UF 16V 16*25" 91.523,49.351 r180 bottom (schematic designator Csm)
Csm_7 "6800uF 16V" "6800UF 16V 16*25" 91.432,32.551 r180 bottom (schematic designator Csm)
Csm_8 "6800uF 16V" "6800uF 16V 16*25" 87.883,15.677 r180 bottom (schematic designator Csm)
D1_1 "B5819W" SOD-123 12.67,73.205 r0 top (schematic designator D1)
D1_2 "B5819W" SOD-123 12.694,56.505 r0 top (schematic designator D1)
D1_3 "B5819W" SOD-123 12.694,39.81 r0 top (schematic designator D1)
D1_4 "B5819W" SOD-123 12.694,23.125 r0 top (schematic designator D1)
D1_5 "B5819W" SOD-123 87.552,58.802 r180 top (schematic designator D1)
D1_6 "B5819W" SOD-123 87.552,42.246 r180 top (schematic designator D1)
D1_7 "B5819W" SOD-123 87.461,25.446 r180 top (schematic designator D1)
D1_8 "B5819W" SOD-123 87.663,8.572 r180 top (schematic designator D1)
D2_1 "B5819W" SOD-123 12.67,64.4 r0 top (schematic designator D2)
D2_2 "B5819W" SOD-123 12.694,47.7 r0 top (schematic designator D2)
D2_3 "B5819W" SOD-123 12.694,31.005 r0 top (schematic designator D2)
D2_4 "B5819W" SOD-123 12.694,14.32 r0 top (schematic designator D2)
D2_5 "B5819W" SOD-123 87.552,67.607 r180 top (schematic designator D2)
D2_6 "B5819W" SOD-123 87.552,51.051 r180 top (schematic designator D2)
D2_7 "B5819W" SOD-123 87.461,34.251 r180 top (schematic designator D2)
D2_8 "B5819W" SOD-123 87.663,17.377 r180 top (schematic designator D2)
D3_1 "LED_灯_红_Iv=100-120_λd=615-630" 0603_LED_S1 22.32,72.905 r180 top (schematic designator D3)
D3_2 "LED_灯_红_Iv=100-120_λd=615-630" 0603_LED_S1 22.343,56.205 r180 top (schematic designator D3)
D3_3 "LED_灯_红_Iv=100-120_λd=615-630" 0603_LED_S1 22.343,39.51 r180 top (schematic designator D3)
D3_4 "LED_灯_红_Iv=100-120_λd=615-630" 0603_LED_S1 22.343,22.825 r180 top (schematic designator D3)
D3_5 "LED_灯_红_Iv=100-120_λd=615-630" 0603_LED_S1 77.903,59.102 r0 top (schematic designator D3)
D3_6 "LED_灯_红_Iv=100-120_λd=615-630" 0603_LED_S1 77.903,42.546 r0 top (schematic designator D3)
D3_7 "LED_灯_红_Iv=100-120_λd=615-630" 0603_LED_S1 77.812,25.746 r0 top (schematic designator D3)
D3_8 "LED_灯_红_Iv=100-120_λd=615-630" 0603_LED_S1 78.013,8.872 r0 top (schematic designator D3)
D4 "LED_灯_红_Iv=100-120_λd=615-630" 0603_LED_S1 59.801,43.805 r270 top
D5 "LED_灯_绿_Iv=112-285_λd=520-535" 0603_LED_S1 57.975,43.805 r270 top
D6 "B5819W" SOD-123 49.8,68.5 r0 top
GND_SM "4MMx1MM5" "PAD WITH HOLE"#1 97.523,21.467 r270 top (schematic designator OUT2)
GND_SM "4MMx1MM5" "PAD WITH HOLE"#2 2.458,60.54 r90 top (schematic designator OUT2)
GND_SM "4MMx1MM5" "PAD WITH HOLE"#1 2.7,43.61 r90 top (schematic designator OUT2)
GND_SM "4MMx1MM5" "PAD WITH HOLE"#1 2.7,26.915 r90 top (schematic designator OUT2)
GND_SM "4MMx1MM5" "PAD WITH HOLE"#1 2.7,10.23 r90 top (schematic designator OUT2)
GND_SM "4MMx1MM5" "PAD WITH HOLE"#3 97.523,71.824 r270 top (schematic designator OUT2)
GND_SM "4MMx1MM5" "PAD WITH HOLE"#1 97.523,55.141 r270 top (schematic designator OUT2)
GND_SM "4MMx1MM5" "PAD WITH HOLE"#1 97.523,38.341 r270 top (schematic designator OUT2)
J1 "10118194-0001LF" FCI-10118194-0001LF-5_V 49.2,3.65 r0 top
L1 "39nH" 0402_L 45.366,47.619 r270 top
L2 "1140-122K-RC" INDRD2921W163D3810H2616P 73,96 r180 bottom
L3 "1140-122K-RC" INDRD2921W163D3810H2616P 27,96 r180 bottom
OUT1_1 "4MMx1MM5" "PAD WITH HOLE"#4 2.528,67.129 r90 top (schematic designator GND1)
OUT1_2 "4MMx1MM5" "PAD WITH HOLE"#1 2.7,51.23 r90 top (schematic designator GND1)
OUT1_3 "4MMx1MM5" "PAD WITH HOLE"#1 2.7,34.535 r90 top (schematic designator GND1)
OUT1_4 "4MMx1MM5" "PAD WITH HOLE"#1 2.7,17.85 r90 top (schematic designator GND1)
OUT1_5 "4MMx1MM5" "PAD WITH HOLE"#5 97.523,64.262 r270 top (schematic designator GND1)
OUT1_6 "4MMx1MM5" "PAD WITH HOLE"#1 97.523,47.521 r270 top (schematic designator GND1)
OUT1_7 "4MMx1MM5" "PAD WITH HOLE"#1 97.523,30.721 r270 top (schematic designator GND1)
OUT1_8 "4MMx1MM5" "PAD WITH HOLE"#1 97.523,13.847 r270 top (schematic designator GND1)
OUT2_1 "4MMx1MM5" "PAD WITH HOLE"#6 1.871,64.781 r90 top (schematic designator Vcap1)
OUT2_2 "4MMx1MM5" "PAD WITH HOLE"#1 2.7,47.42 r90 top (schematic designator Vcap1)
OUT2_3 "4MMx1MM5" "PAD WITH HOLE"#1 2.7,30.725 r90 top (schematic designator Vcap1)
OUT2_4 "4MMx1MM5" "PAD WITH HOLE"#1 2.7,14.04 r90 top (schematic designator Vcap1)
OUT2_5 "4MMx1MM5" "PAD WITH HOLE"#7 97.523,67.503 r270 top (schematic designator Vcap1)
OUT2_6 "4MMx1MM5" "PAD WITH HOLE"#1 97.523,51.331 r270 top (schematic designator Vcap1)
OUT2_7 "4MMx1MM5" "PAD WITH HOLE"#1 97.523,34.531 r270 top (schematic designator Vcap1)
OUT2_8 "4MMx1MM5" "PAD WITH HOLE"#1 97.523,17.657 r270 top (schematic designator Vcap1)
P1_1 "95278-101A06LF" AMPM-95278-101A06LF_V 23.867,70.16 r180 bottom (schematic designator P1)
P1_2 "95278-101A06LF" AMPM-95278-101A06LF_V 23.891,53.46 r180 bottom (schematic designator P1)
P1_3 "95278-101A06LF" AMPM-95278-101A06LF_V 23.891,36.765 r180 bottom (schematic designator P1)
P1_4 "95278-101A06LF" AMPM-95278-101A06LF_V 23.891,20.08 r180 bottom (schematic designator P1)
P1_5 "95278-101A06LF" AMPM-95278-101A06LF_V 76.355,61.847 r0 bottom (schematic designator P1)
P1_6 "95278-101A06LF" AMPM-95278-101A06LF_V 76.355,45.291 r0 bottom (schematic designator P1)
P1_7 "95278-101A06LF" AMPM-95278-101A06LF_V 76.264,28.491 r0 bottom (schematic designator P1)
P1_8 "95278-101A06LF" AMPM-95278-101A06LF_V 76.466,11.617 r0 bottom (schematic designator P1)
P2 "Header 5X2" HDR2.54-LI-2x5P 60.56,4.77 r0 top
P3 "Header 4X2" HDR2.54-LI-2x4P 38.89,4.77 r0 top
P4 "Header 3" HDR2.54-LI-3P 54,57.3 r90 top
P5 "4MMx1MM5" "PAD WITH HOLE"#8 99.645,79.209 r0 top
P6 "4MMx1MM5" "PAD WITH HOLE"#9 97.695,100.432 r0 top
P7 "4MMx1MM5" "PAD WITH HOLE"#10 89.951,78.447 r0 top
P9 "4MMx1MM5" "PAD WITH HOLE"#11 56.572,84.397 r0 top
P10 "4MMx1MM5" "PAD WITH HOLE"#11 56.572,79.266 r0 top
P12 "4MMx1MM5" "PAD WITH HOLE"#12 56.572,74.249 r0 top
P13 "4MMx1MM5" "PAD WITH HOLE"#13 43.4,74.249 r0 top
P14 "4MMx1MM5" "PAD WITH HOLE"#14 43.4,79.266 r0 top
P15 "4MMx1MM5" "PAD WITH HOLE"#15 43.283,84.397 r0 top
P17 "4MMx1MM5" "PAD WITH HOLE"#16 9.795,78.574 r0 top
P18 "4MMx1MM5" "PAD WITH HOLE"#17 1.345,78.574 r0 top
P19 "4MMx1MM5" "PAD WITH HOLE"#18 2.495,100.559 r0 top
Q2 "2N7002" SOT-23(SOT-23-3) 51.25,65.45 r270 top
R1_1 "1KΩ (1001) ±1%" 0402_R 22.69,69.568 r90 top (schematic designator R1)
R1_2 "1KΩ (1001) ±1%" 0402_R 22.713,52.868 r90 top (schematic designator R1)
R1_3 "1KΩ (1001) ±1%" 0402_R 22.713,36.173 r90 top (schematic designator R1)
R1_4 "1KΩ (1001) ±1%" 0402_R 22.713,19.488 r90 top (schematic designator R1)
R1_5 "1KΩ (1001) ±1%" 0402_R 77.533,62.439 r270 top (schematic designator R1)
R1_6 "1KΩ (1001) ±1%" 0402_R 77.533,45.883 r270 top (schematic designator R1)
R1_7 "1KΩ (1001) ±1%" 0402_R 77.442,29.083 r270 top (schematic designator R1)
R1_8 "1KΩ (1001) ±1%" 0402_R 77.643,12.209 r270 top (schematic designator R1)
R2_1 "100KΩ (1003) ±1%" 0402_R 13.72,66.1 r180 top (schematic designator R2)
R2_2 "100KΩ (1003) ±1%" 0402_R 13.744,49.4 r180 top (schematic designator R2)
R2_3 "100KΩ (1003) ±1%" 0402_R 13.744,32.705 r180 top (schematic designator R2)
R2_4 "100KΩ (1003) ±1%" 0402_R 13.744,16.02 r180 top (schematic designator R2)
R2_5 "100KΩ (1003) ±1%" 0402_R 86.502,65.907 r0 top (schematic designator R2)
R2_6 "100KΩ (1003) ±1%" 0402_R 86.502,49.351 r0 top (schematic designator R2)
R2_7 "100KΩ (1003) ±1%" 0402_R 86.411,32.551 r0 top (schematic designator R2)
R2_8 "100KΩ (1003) ±1%" 0402_R 86.613,15.677 r0 top (schematic designator R2)
R3_1 "2.4KΩ (2401) ±1%" 0402_R 19.575,72.915 r180 top (schematic designator R3)
R3_2 "2.4KΩ (2401) ±1%" 0402_R 19.598,56.215 r180 top (schematic designator R3)
R3_3 "2.4KΩ (2401) ±1%" 0402_R 19.598,39.52 r180 top (schematic designator R3)
R3_4 "2.4KΩ (2401) ±1%" 0402_R 19.598,22.835 r180 top (schematic designator R3)
R3_5 "2.4KΩ (2401) ±1%" 0402_R 80.648,59.092 r0 top (schematic designator R3)
R3_6 "2.4KΩ (2401) ±1%" 0402_R 80.648,42.536 r0 top (schematic designator R3)
R3_7 "2.4KΩ (2401) ±1%" 0402_R 80.557,25.736 r0 top (schematic designator R3)
R3_8 "2.4KΩ (2401) ±1%" 0402_R 80.758,8.862 r0 top (schematic designator R3)
R4_1 "47KΩ (4702) ±1%" 0402_R 17.725,68.843 r270 top (schematic designator R4)
R4_2 "47KΩ (4702) ±1%" 0402_R 17.749,52.143 r270 top (schematic designator R4)
R4_3 "47KΩ (4702) ±1%" 0402_R 17.749,35.448 r270 top (schematic designator R4)
R4_4 "47KΩ (4702) ±1%" 0402_R 17.749,18.763 r270 top (schematic designator R4)
R4_5 "47KΩ (4702) ±1%" 0402_R 82.498,63.164 r90 top (schematic designator R4)
R4_6 "47KΩ (4702) ±1%" 0402_R 82.498,46.608 r90 top (schematic designator R4)
R4_7 "47KΩ (4702) ±1%" 0402_R 82.407,29.808 r90 top (schematic designator R4)
R4_8 "47KΩ (4702) ±1%" 0402_R 82.608,12.934 r90 top (schematic designator R4)
R5 "10KΩ (1002) ±1%" 0402_R 56.1,56.825 r90 top
R6 "2.4KΩ (2401) ±1%" 0402_R 58.275,41.55 r180 top
R7 "2.4KΩ (2401) ±1%" 0402_R 56.024,43.175 r180 top
R8 "47Ω (47R0) ±1%" 0402_R 50.018,45.9 r90 top
R11 "1KΩ (1001) ±1%" 0402_R 48.525,64.2 r0 top
U1_1 "SI8641BD-B-ISR" SOIC-16W_SIL 29.45,66.605 r90 top (schematic designator U1)
U1_2 "SI8641BD-B-ISR" SOIC-16W_SIL 29.473,49.905 r90 top (schematic designator U1)
U1_3 "SI8641BD-B-ISR" SOIC-16W_SIL 29.473,33.21 r90 top (schematic designator U1)
U1_4 "SI8641BD-B-ISR" SOIC-16W_SIL 29.473,16.525 r90 top (schematic designator U1)
U1_5 "SI8641BD-B-ISR" SOIC-16W_SIL 70.773,65.402 r270 top (schematic designator U1)
U1_6 "SI8641BD-B-ISR" SOIC-16W_SIL 70.773,48.846 r270 top (schematic designator U1)
U1_7 "SI8641BD-B-ISR" SOIC-16W_SIL 70.682,32.046 r270 top (schematic designator U1)
U1_8 "SI8641BD-B-ISR" SOIC-16W_SIL 70.883,15.172 r270 top (schematic designator U1)
U2_1 "LP1130BSOF" SOP_8_LP1130B 11.412,69.807 r180 top (schematic designator U2)
U2_2 "LP1130BSOF" SOP_8_LP1130B 11.436,53.107 r180 top (schematic designator U2)
U2_3 "LP1130BSOF" SOP_8_LP1130B 11.436,36.412 r180 top (schematic designator U2)
U2_4 "LP1130BSOF" SOP_8_LP1130B 11.436,19.727 r180 top (schematic designator U2)
U2_5 "LP1130BSOF" SOP_8_LP1130B 88.811,62.2 r0 top (schematic designator U2)
U2_6 "LP1130BSOF" SOP_8_LP1130B 88.811,45.644 r0 top (schematic designator U2)
U2_7 "LP1130BSOF" SOP_8_LP1130B 88.72,28.844 r0 top (schematic designator U2)
U2_8 "LP1130BSOF" SOP_8_LP1130B 88.921,11.97 r0 top (schematic designator U2)
U3_1 "ATTINY10-TSHR" 6ST1_ATM 20.1,69.624 r180 top (schematic designator U3)
U3_2 "ATTINY10-TSHR" 6ST1_ATM 20.123,52.924 r180 top (schematic designator U3)
U3_3 "ATTINY10-TSHR" 6ST1_ATM 20.123,36.229 r180 top (schematic designator U3)
U3_4 "ATTINY10-TSHR" 6ST1_ATM 20.123,19.544 r180 top (schematic designator U3)
U3_5 "ATTINY10-TSHR" 6ST1_ATM 80.123,62.383 r0 top (schematic designator U3)
U3_6 "ATTINY10-TSHR" 6ST1_ATM 80.123,45.827 r0 top (schematic designator U3)
U3_7 "ATTINY10-TSHR" 6ST1_ATM 80.032,29.027 r0 top (schematic designator U3)
U3_8 "ATTINY10-TSHR" 6ST1_ATM 80.233,12.153 r0 top (schematic designator U3)
U4_1 "LP1130BSOF" SOP_8_LP1130B 11.412,61 r180 top (schematic designator U4)
U4_2 "LP1130BSOF" SOP_8_LP1130B 11.436,44.3 r180 top (schematic designator U4)
U4_3 "LP1130BSOF" SOP_8_LP1130B 11.436,27.605 r180 top (schematic designator U4)
U4_4 "LP1130BSOF" SOP_8_LP1130B 11.436,10.92 r180 top (schematic designator U4)
U4_5 "LP1130BSOF" SOP_8_LP1130B 88.811,71.007 r0 top (schematic designator U4)
U4_6 "LP1130BSOF" SOP_8_LP1130B 88.811,54.451 r0 top (schematic designator U4)
U4_7 "LP1130BSOF" SOP_8_LP1130B 88.72,37.651 r0 top (schematic designator U4)
U4_8 "LP1130BSOF" SOP_8_LP1130B 88.921,20.777 r0 top (schematic designator U4)
U5 "STM32F407VET6" LQFP-100_14x14x05P 50,34 r180 top locked
U6 "ACS712ELCTR-05B-T" SOIC-8_150mil 60.898,76.1 r180 top
U7 "V23105A5001A201" RELAY_V23105A5001A201 46.1,66.732 r90 bottom
U8 "ACS712ELCTR-05B-T" SOIC-8_150mil 38.635,76.1 r180 top
VCap_1 "4MMx1MM5" "PAD WITH HOLE"#19 2.458,72.37 r90 top (schematic designator OUT1)
VCap_2 "4MMx1MM5" "PAD WITH HOLE"#1 2.7,55.04 r90 top (schematic designator OUT1)
VCap_3 "4MMx1MM5" "PAD WITH HOLE"#1 2.7,38.345 r90 top (schematic designator OUT1)
VCap_4 "4MMx1MM5" "PAD WITH HOLE"#1 2.7,21.66 r90 top (schematic designator OUT1)
VCap_5 "4MMx1MM5" "PAD WITH HOLE"#3 97.523,60.394 r270 top (schematic designator OUT1)
VCap_6 "4MMx1MM5" "PAD WITH HOLE"#1 97.523,43.711 r270 top (schematic designator OUT1)
VCap_7 "4MMx1MM5" "PAD WITH HOLE"#1 97.523,26.911 r270 top (schematic designator OUT1)
VCap_8 "4MMx1MM5" "PAD WITH HOLE"#1 97.523,10.037 r270 top (schematic designator OUT1)
VR1_1 "B0512S-1W" B0512S-1W 33.35,59.405 r180 bottom (schematic designator VR1)
VR1_2 "B0512S-1W" B0512S-1W 33.373,42.705 r180 bottom (schematic designator VR1)
VR1_3 "B0512S-1W" B0512S-1W 33.373,26.01 r180 bottom (schematic designator VR1)
VR1_4 "B0512S-1W" B0512S-1W 33.373,9.325 r180 bottom (schematic designator VR1)
VR1_5 "B0512S-1W" B0512S-1W 66.873,72.602 r0 bottom (schematic designator VR1)
VR1_6 "B0512S-1W" B0512S-1W 66.873,56.046 r0 bottom (schematic designator VR1)
VR1_7 "B0512S-1W" B0512S-1W 66.782,39.246 r0 bottom (schematic designator VR1)
VR1_8 "B0512S-1W" B0512S-1W 66.983,22.372 r0 bottom (schematic designator VR1)
VR2 "HT7533-1" SOT-89(SOT-89-3) 43.064,11.935 r0 top
VR2_1 "78L05G-AB3-R" SOT-89(SOT-89-3) 18.216,60.562 r180 top (schematic designator VR2)
VR2_2 "78L05G-AB3-R" SOT-89(SOT-89-3) 18.24,43.862 r180 top (schematic designator VR2)
VR2_3 "78L05G-AB3-R" SOT-89(SOT-89-3) 18.24,27.167 r180 top (schematic designator VR2)
VR2_4 "78L05G-AB3-R" SOT-89(SOT-89-3) 18.24,10.482 r180 top (schematic designator VR2)
VR2_5 "78L05G-AB3-R" SOT-89(SOT-89-3) 82.007,71.445 r0 top (schematic designator VR2)
VR2_6 "78L05G-AB3-R" SOT-89(SOT-89-3) 82.007,54.889 r0 top (schematic designator VR2)
VR2_7 "78L05G-AB3-R" SOT-89(SOT-89-3) 81.916,38.089 r0 top (schematic designator VR2)
VR2_8 "78L05G-AB3-R" SOT-89(SOT-89-3) 82.117,21.215 r0 top (schematic designator VR2)
Y1 "16MHZ 9PF 10PPM" SMD-3225_4P 51.5,48.8 r180 top

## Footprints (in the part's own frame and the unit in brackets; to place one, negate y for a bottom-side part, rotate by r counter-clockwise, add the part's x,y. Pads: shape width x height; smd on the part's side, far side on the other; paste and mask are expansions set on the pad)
6ST1_ATM [mil] "ATTINY10"
  rect 22x50 smd: 1(-37.4,-48) 2(0,-48) 3(37.4,-48) 4(37.4,48) 5(0,48) 6(-37.4,48)
  silkscreen extent -77,-72 64,40, body extent -59,-59 59,59, height 58
0402_C [mm]
  rect 0.6x0.65 smd mask+0.051: 1(-0.425,0) 2(0.425,0)
  silkscreen extent -0.97,-0.58 0.97,0.58, body extent -0.48,-0.3 0.52,0.3, height 0.2
0402_L [mm]
  rect 0.6x0.65 smd: 1(-0.425,0) 2(0.425,0)
  silkscreen extent -0.98,-0.58 0.98,0.57, body extent -0.49,-0.26 0.52,0.26, height 0.36
0402_R [mm]
  rect 0.6x0.65 smd mask+0.051: 1(-0.425,0) 2(0.425,0)
  silkscreen extent -0.97,-0.58 0.97,0.58, body extent -0.57,-0.27 0.58,0.28, height 0.41
0603_C [mm]
  rect 0.93x0.98 smd: 1(-0.77,0) 2(0.77,0)
  silkscreen extent -1.53,-0.79 1.54,0.79, body extent -0.8,-0.4 0.8,0.4, height 0.3
0603_LED_S1 [mm]
  rect 0.93x0.98 smd: A(0.77,0) K(-0.77,0)
  silkscreen extent -1.98,-0.79 1.54,0.79, body extent -0.8,-0.4 0.8,0.4, height 0.6
"6800UF 16V 16*25" [mm] "LCSC C47893"
  rect 1.3x1.3 hole 0.8: 1(0,0)
  round 1.3 hole 0.8: 2(7.5,0)
  silkscreen extent -4.25,-8 11.75,8, body extent -4.25,-8 11.75,8, height 32.01
"6800uF 16V 16*25" [mm] "LCSC C47893"
  rect 1.3x1.3 hole 0.8: 1(-3.75,0)
  round 1.3 hole 0.8: 2(3.75,0)
  silkscreen extent -8,-8 8,8, body extent -8,-8 8,8, height 32.01
AMPM-95278-101A06LF_V [mil] "SMD, 6-Leads, Body 7.26x4.83mm, Pitch 2.54mm"
  rect 50x100 smd: 1(-100,-107.48) 2(-100,107.48) 3(0,-107.48) 4(0,107.48) 5(100,-107.48) 6(100,107.48)
  silkscreen extent -143,-182 143,95, body extent -142,-143 142,143, height 382
B0512S-1W [mm]
  rect 1.5x1.5 hole 0.9: 1(0,0)
  round 1.5 hole 0.9: 2(2.54,0) 3(5.08,0) 4(7.62,0)
  silkscreen extent -1.99,-0.9 9.61,5.1, body extent -1.94,-0.9 9.56,5.1, height 10.6
FCI-10118194-0001LF-5_V [mm] "SMD, 5-Leads, Body 7x5mm, Pitch 0.65 mm"
  rect 0.4x1.35 smd: 1(-1.3,1.35) 2(-0.65,1.35) 3(0,1.35) 4(0.65,1.35) 5(1.3,1.35)
  oval 1.25x0.95 hole 0.55 slot 0.85 at 0 deg: 6(-2.5,1.35) 7(2.5,1.35)
  oval 0.9x1.55 hole 0.5 slot 1.15 at 90 deg: 8(-3.5,-1.35) 9(3.5,-1.35)
  rect 1.5x1.55 smd: 10(-1,-1.35) 11(1,-1.35)
  TOP01 region: -2.3,-2.125 -2.3,-0.575 -3.5,-0.575 -3.5,-2.125
  TOP01 region: 3.5,-2.125 3.5,-0.575 2.3,-0.575 2.3,-2.125
  silkscreen extent -3.5,-3.5 3.5,2.72, body extent -4.03,-4.03 4.02,1.55, height 2.72
HDR2.54-LI-2x4P [mm] "双排排针，4x2脚"
  rect 1.6x1.6 hole 0.9: 1(-3.81,-1.27)
  round 1.6 hole 0.9: 2(-3.81,1.27) 3(-1.27,-1.27) 4(-1.27,1.27) 5(1.27,-1.27) 6(1.27,1.27) 7(3.81,-1.27) 8(3.81,1.27)
  silkscreen extent -5.08,-2.54 5.08,2.54, body extent -5.08,-2.54 5.08,2.54, height 8.5
HDR2.54-LI-2x5P [mm] "双排排针，5x2脚"
  rect 1.6x1.6 hole 0.9: 1(-5.08,-1.27)
  round 1.6 hole 0.9: 2(-5.08,1.27) 3(-2.54,-1.27) 4(-2.54,1.27) 5(0,-1.27) 6(0,1.27) 7(2.54,-1.27) 8(2.54,1.27) 9(5.08,-1.27) 10(5.08,1.27)
  silkscreen extent -6.35,-2.54 6.35,2.54, body extent -6.35,-2.54 6.35,2.54, height 8.5
HDR2.54-LI-3P [mm] "排针，3脚"
  rect 1.7x1.7 hole 0.9: 1(-2.54,0)
  round 1.7 hole 0.9: 2(0,0) 3(2.54,0)
  silkscreen extent -3.81,-1.27 3.81,1.27, body extent -3.81,-1.27 3.81,1.27, height 8.5
INDRD2921W163D3810H2616P [mm]
  round 2.8 hole 1.85: 1(-14.605,0) 2(14.605,0)
  silkscreen extent -19.05,-19.05 19.05,19.05, body extent -19.05,-19.05 19.05,19.05, height 26.23
LQFP-100_14x14x05P [mm]
  oval 0.28x1.8 smd: 1(-6,-7.55) 2(-5.5,-7.55) 3(-5,-7.55) 4(-4.5,-7.55) 5(-4,-7.55) 6(-3.5,-7.55) 7(-3,-7.55) 8(-2.5,-7.55) 9(-2,-7.55) 10(-1.5,-7.55) 11(-1,-7.55) 12(-0.5,-7.55) 13(0,-7.55) 14(0.5,-7.55) 15(1,-7.55) 16(1.5,-7.55) 17(2,-7.55) 18(2.5,-7.55) 19(3,-7.55) 20(3.5,-7.55) 21(4,-7.55) 22(4.5,-7.55) 23(5,-7.55) 24(5.5,-7.55) 25(6,-7.55) 51(6,7.55) 52(5.5,7.55) 53(5,7.55) 54(4.5,7.55) 55(4,7.55) 56(3.5,7.55) 57(3,7.55) 58(2.5,7.55) 59(2,7.55) 60(1.5,7.55) 61(1,7.55) 62(0.5,7.55) 63(0,7.55) 64(-0.5,7.55) 65(-1,7.55) 66(-1.5,7.55) 67(-2,7.55) 68(-2.5,7.55) 69(-3,7.55) 70(-3.5,7.55) 71(-4,7.55) 72(-4.5,7.55) 73(-5,7.55) 74(-5.5,7.55) 75(-6,7.55)
  oval 1.8x0.28 smd: 26(7.55,-6) 27(7.55,-5.5) 28(7.55,-5) 29(7.55,-4.5) 30(7.55,-4) 31(7.55,-3.5) 32(7.55,-3) 33(7.55,-2.5) 34(7.55,-2) 35(7.55,-1.5) 36(7.55,-1) 37(7.55,-0.5) 38(7.55,0) 39(7.55,0.5) 40(7.55,1) 41(7.55,1.5) 42(7.55,2) 43(7.55,2.5) 44(7.55,3) 45(7.55,3.5) 46(7.55,4) 47(7.55,4.5) 48(7.55,5) 49(7.55,5.5) 50(7.55,6) 76(-7.55,6) 77(-7.55,5.5) 78(-7.55,5) 79(-7.55,4.5) 80(-7.55,4) 81(-7.55,3.5) 82(-7.55,3) 83(-7.55,2.5) 84(-7.55,2) 85(-7.55,1.5) 86(-7.55,1) 87(-7.55,0.5) 88(-7.55,0) 89(-7.55,-0.5) 90(-7.55,-1) 91(-7.55,-1.5) 92(-7.55,-2) 93(-7.55,-2.5) 94(-7.55,-3) 95(-7.55,-3.5) 96(-7.55,-4) 97(-7.55,-4.5) 98(-7.55,-5) 99(-7.55,-5.5) 100(-7.55,-6)
  silkscreen extent -6.75,-8.15 6.25,6.25, body extent -8,-8 8,8, height 1.6
"PAD WITH HOLE"#1 [mm]
  round 2.5 hole 1.5: 1(0,0)
"PAD WITH HOLE"#2 [mm]
  round 2.5 hole 1.5: 1(-0.23,-0.242)
"PAD WITH HOLE"#3 [mm]
  round 2.5 hole 1.5: 1(0.127,0)
"PAD WITH HOLE"#4 [mm]
  round 2.5 hole 1.5: 1(0.801,-0.172)
"PAD WITH HOLE"#5 [mm]
  round 2.5 hole 1.5: 1(0.186,0)
"PAD WITH HOLE"#6 [mm]
  round 2.5 hole 1.5: 1(-0.661,-0.829)
"PAD WITH HOLE"#7 [mm]
  round 2.5 hole 1.5: 1(-0.384,0)
"PAD WITH HOLE"#8 [mm]
  round 2.5 hole 1.5: 1(-2.439,-0.678)
"PAD WITH HOLE"#9 [mm]
  round 5 hole 2.7: 1(-0.895,-13.132)
"PAD WITH HOLE"#10 [mm]
  round 2.5 hole 1.5: 1(-2.061,0.084)
"PAD WITH HOLE"#11 [mm]
  round 2.5 hole 1.5: 1(-0.172,0)
"PAD WITH HOLE"#12 [mm]
  round 2.5 hole 1.5: 1(-4.572,18.751)
"PAD WITH HOLE"#13 [mm]
  round 2.5 hole 1.5: 1(4.6,18.751)
"PAD WITH HOLE"#14 [mm]
  round 2.5 hole 1.5: 1(0.2,0)
"PAD WITH HOLE"#15 [mm]
  round 2.5 hole 1.5: 1(0.317,0)
"PAD WITH HOLE"#16 [mm]
  round 2.5 hole 1.5: 1(2.3,-0.043)
"PAD WITH HOLE"#17 [mm]
  round 2.5 hole 1.5: 1(1.855,-0.043)
"PAD WITH HOLE"#18 [mm]
  round 5 hole 2.7: 1(0.705,-13.259)
"PAD WITH HOLE"#19 [mm]
  round 2.5 hole 1.5: 1(-0.63,-0.242)
RELAY_V23105A5001A201 [mil] "V23105A5001A201"
  rect 60x60 hole 30: 1(-0.98,0)
  round 60 hole 30: 4(299.02,0) 6(499.02,0) 8(699.02,0) 9(699.02,300) 11(499.02,300) 13(299.02,300) 16(-0.98,300)
  silkscreen extent -45,-67 746,348, body extent -45,-41 746,348, height 426
SMD-3225_4P [mm]
  rect 1.4x1.15 smd: 1(-1.1,-0.8) 2(1.1,-0.8) 3(1.1,0.8) 4(-1.1,0.8)
  silkscreen extent -2.59,-2.21 2.1,1.7, body extent -1.6,-1.25 1.6,1.25, height 0.61
SOD-123 [mm]
  rect 1.25x1 smd: 1(1.475,0) 2(-1.475,0)
  silkscreen extent -0.5,-0.7 0.5,0.7, body extent -1.85,-0.77 1.85,0.78, height 1.35
SOIC-8_150mil [mm]
  oval 0.7x1.8 smd: 1(-1.905,-2.6) 2(-0.635,-2.6) 3(0.635,-2.6) 4(1.905,-2.6) 5(1.905,2.6) 6(0.635,2.6) 7(-0.635,2.6) 8(-1.905,2.6)
  silkscreen extent -2.9,-3.05 2.4,1.4
SOIC-16W_SIL [mm] "SI8641BD-B-ISR"
  rect 0.6x1.9 smd: 1(-4.445,-4.7) 2(-3.175,-4.7) 3(-1.905,-4.7) 4(-0.635,-4.7) 5(0.635,-4.7) 6(1.905,-4.7) 7(3.175,-4.7) 8(4.445,-4.7) 9(4.445,4.7) 10(3.175,4.7) 11(1.905,4.7) 12(0.635,4.7) 13(-0.635,4.7) 14(-1.905,4.7) 15(-3.175,4.7) 16(-4.445,4.7)
  silkscreen extent -5.39,-4.88 5.28,3.87, body extent -5.16,-5.3 5.16,5.3, height 2.64
SOP_8_LP1130B [mm]
  oval 1.45x0.6 smd: 1(-2.725,1.905) 2(-2.725,0.635) 3(-2.725,-0.635) 4(-2.725,-1.905) 5(2.725,-1.905) 6(2.725,-0.635) 7(2.725,0.635) 8(2.725,1.905)
  silkscreen extent -2.85,-2.5 1.6,2.88, body extent -3,-2.5 3,2.5, height 1.75
SOT23-6L_STM [mil] "USBLC62SC6"
  rect 22x38.5 smd paste+0 mask+0: 1(-37.4,-53.75) 2(0,-53.75) 3(37.4,-53.75) 4(37.4,53.75) 5(0,53.75) 6(-37.4,53.75)
  silkscreen extent -72,-62 64,40, body extent -59,-64 59,54, height 57
SOT-23(SOT-23-3) [mm]
  rect 1.25x0.7 smd: 1(1.25,-0.95) 2(1.25,0.95) 3(-1.25,0)
  silkscreen extent -0.65,-1.96 1.96,1.46, body extent -1.5,-1.5 1.5,1.5, height 1.3
SOT-89(SOT-89-3) [mm]
  oval 1.9x0.7 smd: 1(0,-1.5) 3(0,1.5)
  oval 3.5x2 smd: 2(-2.5,0)
  oval 2.1x0.7 smd: 2(-0.1,0)
  silkscreen extent -3.1,-2.47 0.18,2.3, body extent -3.75,-2.25 0.55,2.25, height 1.51

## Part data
C1_1 C1_2 C1_3 C1_4 C1_5 C1_6 C1_7 C1_8: "C15525 6.3V 0402", Package=0402, SuppliersPartNumber=C15525
C2_1 C2_2 C2_3 C2_4 C2_5 C2_6 C2_7 C2_8 C10 C11: "C15525 贴片电容 0402", Package=0402, SuppliersPartNumber=C15525
C3_1 C3_2 C3_3 C3_4 C3_5 C3_6 C3_7 C3_8 C5_1 C5_2 C5_3 C5_4 C5_5 C5_6 C5_7 C5_8 C6_1 C6_2 C6_3 C6_4 C6_5 C6_6 C6_7 C6_8 C8_1 C8_2 C8_3 C8_4 C8_5 C8_6 C8_7 C8_8 C11_1 C11_2 C11_3 C11_4 C11_5 C11_6 C11_7 C11_8 C12_1 C12_2 C12_3 C12_4 C12_5 C12_6 C12_7 C12_8 C19: "C52923 贴片电容 0402", Package=0402, SuppliersPartNumber=C52923
C4_1 C4_2 C4_3 C4_4 C4_5 C4_6 C4_7 C4_8: library part 10uF, "C92487 10uF 16V 0603", Package=0603, SuppliersPartNumber=C19702
C7_1 C7_2 C7_3 C7_4 C7_5 C7_6 C7_7 C7_8 C9_1 C9_2 C9_3 C9_4 C9_5 C9_6 C9_7 C9_8 C10_1 C10_2 C10_3 C10_4 C10_5 C10_6 C10_7 C10_8 C13 C14 C15 C16 C17 C18 C20 C26 C28: "C1525 贴片电容 0402", Package=0402, SuppliersPartNumber=C1525
C12: "C23733 贴片电容 0402", Package=0402, SuppliersPartNumber=C23733
C21 C22: "C1547 贴片电容 0402", Package=0402, SuppliersPartNumber=C1547
C23 C24: "C23630 贴片电容 0603", Package=0603, SuppliersPartNumber=C23630
C25 C27: "C1523 贴片电容 0402", Package=0402, SuppliersPartNumber=C1523
CR1: "C7519 SOT-23-6L"
Csm_1 Csm_2 Csm_3 Csm_4 Csm_5 Csm_6 Csm_7 Csm_8: "C47893 引线型铝电解电容 Radial,16x25mm", Manufacturer 1=KEMET, Manufacturer Part Number 1=ESK688M010AM2AA
D1_1 D1_2 D1_3 D1_4 D1_5 D1_6 D1_7 D1_8 D2_1 D2_2 D2_3 D2_4 D2_5 D2_6 D2_7 D2_8 D6: "C8598 SOD-123", Package=SOD-123, SuppliersPartNumber=C8598
D3_1 D3_2 D3_3 D3_4 D3_5 D3_6 D3_7 D3_8 D4: "C2286 发光二极管 LED_0603", Package=0603, SuppliersPartNumber=C2286
D5: "C72043 发光二极管 LED_0603", Package=0603, SuppliersPartNumber=C72043
GND_SM GND_SM GND_SM GND_SM GND_SM GND_SM GND_SM GND_SM OUT1_1 OUT1_2 OUT1_3 OUT1_4 OUT1_5 OUT1_6 OUT1_7 OUT1_8 OUT2_1 OUT2_2 OUT2_3 OUT2_4 OUT2_5 OUT2_6 OUT2_7 OUT2_8 P5 P6 P7 P9 P10 P12 P13 P14 P15 P17 P18 P19 VCap_1 VCap_2 VCap_3 VCap_4 VCap_5 VCap_6 VCap_7 VCap_8: library part PAD_WITH_HOLE_4MMx1MM5, "PAD_WITH_HOLE_4MMx1MM5"
J1: "C132563", Manufacturer="Amphenol FCI", Package Description="5-Pin Surface Mount Device, Body 8.05 x 5.53 mm, Pitch 0.65 mm", Package Reference=10118194-0001LF-5
L1: "C26443 贴片电感 0402", Package=0402, SuppliersPartNumber=C26443
L2 L3: "C1329703 Radial", Package="Radial Bourns"
P1_1 P1_2 P1_3 P1_4 P1_5 P1_6 P1_7 P1_8: "C178294", Case Code (Imperial)=0603, Case Code (Metric)=1608, Manufacturer="Amphenol FCI", Max Operating Temperature="155 degC", Min Operating Temperature="-55 degC", Power Rating="100 mW", Resistance="49.9 Ohm", Tolerance=1%, Voltage Rating="50 V"
P2: "C124387"
P3: "C124386"
P4: "C124376"
Q2: "C8545 SOT-23-3", Package=SOT-23(SOT-23-3), SuppliersPartNumber=C8545
R1_1 R1_2 R1_3 R1_4 R1_5 R1_6 R1_7 R1_8 R11: "C11702 贴片电阻 0402", Package=0402, SuppliersPartNumber=C11702
R2_1 R2_2 R2_3 R2_4 R2_5 R2_6 R2_7 R2_8: "C25741 贴片电阻 0402", Package=0402, SuppliersPartNumber=C25741
R3_1 R3_2 R3_3 R3_4 R3_5 R3_6 R3_7 R3_8 R6 R7: "C25882 贴片电阻 0402", Package=0402, SuppliersPartNumber=C25882
R4_1 R4_2 R4_3 R4_4 R4_5 R4_6 R4_7 R4_8: "C25792 贴片电阻 0402", Package=0402, SuppliersPartNumber=C25792
R5: "C25744 贴片电阻 0402", Package=0402, SuppliersPartNumber=C25744
R8: "C25118 贴片电阻 0402", Package=0402, SuppliersPartNumber=C25118
U1_1 U1_2 U1_3 U1_4 U1_5 U1_6 U1_7 U1_8: "C461891 SOIC-16_7.5X10.3X1.27P Extended"
U2_1 U2_2 U2_3 U2_4 U2_5 U2_6 U2_7 U2_8 U4_1 U4_2 U4_3 U4_4 U4_5 U4_6 U4_7 U4_8: "C387697 SOP-8_EP_3.9X4.9X1.27P"
U3_1 U3_2 U3_3 U3_4 U3_5 U3_6 U3_7 U3_8: "C128438 SOT-23-6L Extended"
U5: "C28730 ARM", Package=LQFP-100_14x14x05P, SuppliersPartNumber=C28730
U6 U8: "C44471 电流传感器 SOIC-8_3.9X4.9X1.27P", Package=SOIC-8_150mil, SuppliersPartNumber=C44471
U7: "3A 5V", Coil Current=29.76mA, Coil Power=150mW, Coil Resistance=167R, Coil Voltage (DC)=5V, Contact Current Rating=3A, Contact Voltage Rating (DC)=220V, Manufacturer="TE Connectivity Axicom", Max Operating Temperature=85°C, Max Voltage Rating (AC)=250V, Min Operating Temperature=-40°C, Package Quantity=25, Ratings=IP67, Supplier Part Number 1=655-V23105A5001A201
VR1_1 VR1_2 VR1_3 VR1_4 VR1_5 VR1_6 VR1_7 VR1_8: "Isolated DCDC 0512 C133158"
VR2: "C14289 低压差线性稳压(LDO) SOT-89", Package=SOT-89, SuppliersPartNumber=C14289
VR2_1 VR2_2 VR2_3 VR2_4 VR2_5 VR2_6 VR2_7 VR2_8: "C71136 低压差线性稳压(LDO) SOT-89  12-5", Package=SOT-89, SuppliersPartNumber=C71136
Y1: "C13738 贴片晶振", Package=SMD-3225_4P, SuppliersPartNumber=C13738

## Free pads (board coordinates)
  round 0 hole 3.4 unplated: Support(4,4) Support(4,96) Support(96,4) Support(96,96)

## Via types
v1: diameter 0.5, hole 0.25, TOP01 to BOTTOM04, tented both sides, 760 vias
v2: diameter 1.2, hole 0.6, TOP01 to BOTTOM04, 35 vias
v3: diameter 0.6, hole 0.3, TOP01 to BOTTOM04, tented both sides, 12 vias
v4: diameter 0.5, hole 0.25, TOP01 to BOTTOM04, 10 vias

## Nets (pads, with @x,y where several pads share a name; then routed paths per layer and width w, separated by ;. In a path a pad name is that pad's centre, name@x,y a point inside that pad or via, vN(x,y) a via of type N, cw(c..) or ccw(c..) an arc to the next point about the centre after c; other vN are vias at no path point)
3.3V_MC: C11.2 C12.2 C13.2 C14.2 C15.2 C16.2 C17.2 C18.2 L1.1 P2.1 P4.1 U5.6 U5.11 U5.19 U5.28 U5.50 U5.75 U5.100 VR2.3 | length 26.7
  TOP01 w0.254: v1(40.4,38.4) C12.2@40.4,39 U5.28@42.45,39 ; C13.2@42.134,26.786 42.134,27.988 42.146,28 U5.50@42.45,28 ; U5.19@47,41.55 C18.2@47,43.474 ; C18.2@47.14,43.3 47.313,43.473 47.313,43.72 47.401,43.808 v1(47.401,43.875) ; U5.11@51,41.55 51,42.749 C16.2@51.401,43.15 ; C16.2@51.401,43.175 v1(51.401,43.75) ; v1(53.5,40.25) U5.6@53.5,41.55 ; U5.75@56,26.45 56.009,26.441 C14.2@57.2,26.441 57.204,26.446 57.771,26.446 v1(57.775,26.45) ; U5.100@57.55,40 57.558,40.008 58.318,40.008 58.649,40.339 C15.2@59.311,40.339 v1(59.886,40.339)
  TOP01 w0.381: C13.2@42.134,26.786 42.148,26.8 42.173,26.8 v1@42.6,26.8
  TOP01 w0.762: v1(53.2,14.3) 53.2,5.92 P2.1@55.46,3.66
  other v1: 44.72,13.5 45.92,13.5 50.4,13.5 53.2,13.5 40.7,14.3 41.597,14.3 42.493,14.3 43.39,14.3 45.92,14.3 50.4,14.3 42.7,26.8 45.366,48.594 46.726,48.594
3.3VA: C19.1 C20.2 L1.2 U5.21 U5.22 | length 0.1
  TOP01 w0.152: C20.2@45.475,44.7 C20.2@45.5,44.675 ; C19.1@45.475,45.9 C19.1@45.5,45.925
+5: C1_1.2 C1_2.2 C1_3.2 C1_4.2 C1_5.2 C1_6.2 C1_7.2 C1_8.2 C7_1.2 C7_2.2 C7_3.2 C7_4.2 C7_5.2 C7_6.2 C7_7.2 C7_8.2 C10.2 C26.2 C28.2 CR1.5 D6.2 J1.1 P3.2 U1_1.1 U1_1.7 U1_2.1 U1_2.7 U1_3.1 U1_3.7 U1_4.1 U1_4.7 U1_5.1 U1_5.7 U1_6.1 U1_6.7 U1_7.1 U1_7.7 U1_8.1 U1_8.7 U6.8 U7.1 U8.8 VR1_1.2 VR1_2.2 VR1_3.2 VR1_4.2 VR1_5.2 VR1_6.2 VR1_7.2 VR1_8.2 VR2.2 | length 47
  TOP01 w0.152: VR1_4.2@30.833,9.325 VR1_4.2@30.833,9.426 ; U7.1@46.1,66.707 46.786,67.393 46.893,67.393 ; C1_8.2@68.683,21.077 68.758,21.152 C1_8.2@68.856,21.25 ; VR1_5.2@69.169,72.358 VR1_5.2@69.413,72.602
  TOP01 w0.254: U1_8.7@66.183,11.997 U1_8.7@66.185,11.998 ; v1(67.7,12) v1(67.7,12)
  TOP01 w0.381: v1(32.7,19.7) U1_4.7@34.173,19.7 ; v1(32.7,69.8) 32.71,69.79 34.14,69.79 U1_1.7@34.15,69.78 ; v1(32.8,36.4) 32.808,36.392 34.166,36.392 U1_3.7@34.173,36.385 ; v1(32.8,53.1) 32.81,53.09 34.163,53.09 U1_2.7@34.173,53.08 ; U1_1.1@34.15,62.16 C7_1.2@35.905,62.16 ; U1_3.1@34.173,28.765 C7_3.2@35.928,28.765 ; U1_2.1@34.173,45.46 C7_2.2@35.928,45.46 ; C7_1.2@35.925,62.18 C7_1.2@35.95,62.18 35.977,62.152 35.977,61.623 v1(36,61.6) ; C7_3.2@35.948,28.785 C7_3.2@35.973,28.785 35.987,28.771 35.987,28.213 v1(36,28.2) ; C7_2.2@35.948,45.48 C7_2.2@35.973,45.48 35.987,45.466 35.987,44.913 v1(36,44.9) ; U8.8@40.54,73.5 C28.2@40.54,71.75 v1(41.115,71.75) ; v1(47.9,3.9) J1.1@47.9,5 ; C26.2@62.803,71.825 U6.8@62.803,73.5 ; C7_7.2@64.182,36.471 64.191,36.48 64.191,36.991 v1(64.2,37) ; C7_7.2@64.227,36.491 U1_7.1@65.982,36.491 ; C7_6.2@64.273,53.271 64.287,53.284 64.287,53.887 v1(64.3,53.9) ; C7_6.2@64.318,53.291 U1_6.1@66.073,53.291 ; C7_8.2@64.383,19.597 64.392,19.605 64.392,20.192 v1(64.4,20.2) ; C7_8.2@64.428,19.617 U1_8.1@66.183,19.617 ; U1_7.7@65.982,28.871 65.997,28.885 67.485,28.885 v1(67.5,28.9) ; U1_6.7@66.073,45.671 66.102,45.7 v1(67.4,45.7) ; U1_5.7@66.073,62.227 66.087,62.213 67.487,62.213 v1(67.5,62.2) ; U1_8.7@66.185,11.998 v1(67.7,12)
  TOP01 w0.508: VR1_1.2@30.81,59.405 30.81,59.535 31.604,60.329 31.604,60.654 C1_1.2@31.65,60.7 ; VR1_4.2@30.833,9.325 31.628,10.119 C1_4.2@31.628,10.574 ; VR1_3.2@30.833,26.01 31.628,26.804 31.628,27.259 C1_3.2@31.674,27.305 ; VR1_2.2@30.833,42.705 31.628,43.499 31.628,43.954 C1_2.2@31.674,44 ; C1_7.2@68.548,37.951 68.594,37.997 68.594,38.487 69.322,39.216 VR1_7.2@69.322,39.246 ; C1_6.2@68.573,54.751 68.619,54.797 68.619,55.122 69.413,55.916 VR1_6.2@69.413,56.046 ; C1_5.2@68.573,71.307 68.619,71.353 68.619,71.808 VR1_5.2@69.169,72.358 ; C1_8.2@68.683,21.077 68.729,21.123 68.729,21.465 69.523,22.259 VR1_8.2@69.523,22.372
  TOP01 w0.762: 46.893,67.499 47.974,68.581 D6.2@48.206,68.581
  other v1: 34.9,11.3 36.4,11.3 38.42,11.3 45.92,11.338 32.6,12 38.42,12.312 44.014,12.312 44.967,12.312 45.92,12.312 67.8,19.6 32.7,28.6 67.6,36.7 32.7,45.2 67.5,53.5 32.8,61.9 47.2,67.8 67.9,70 64.3,70.4 64,71.9 64,73.3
